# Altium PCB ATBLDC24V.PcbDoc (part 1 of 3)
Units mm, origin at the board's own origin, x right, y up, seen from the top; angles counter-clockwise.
Board outline 135 x 125 mm, 4 copper layers (Top Layer, GND, PWR/Signal, Bottom Layer), stack 1.716 mm thick; 340 components, 168 nets, 921 pads, 872 vias.
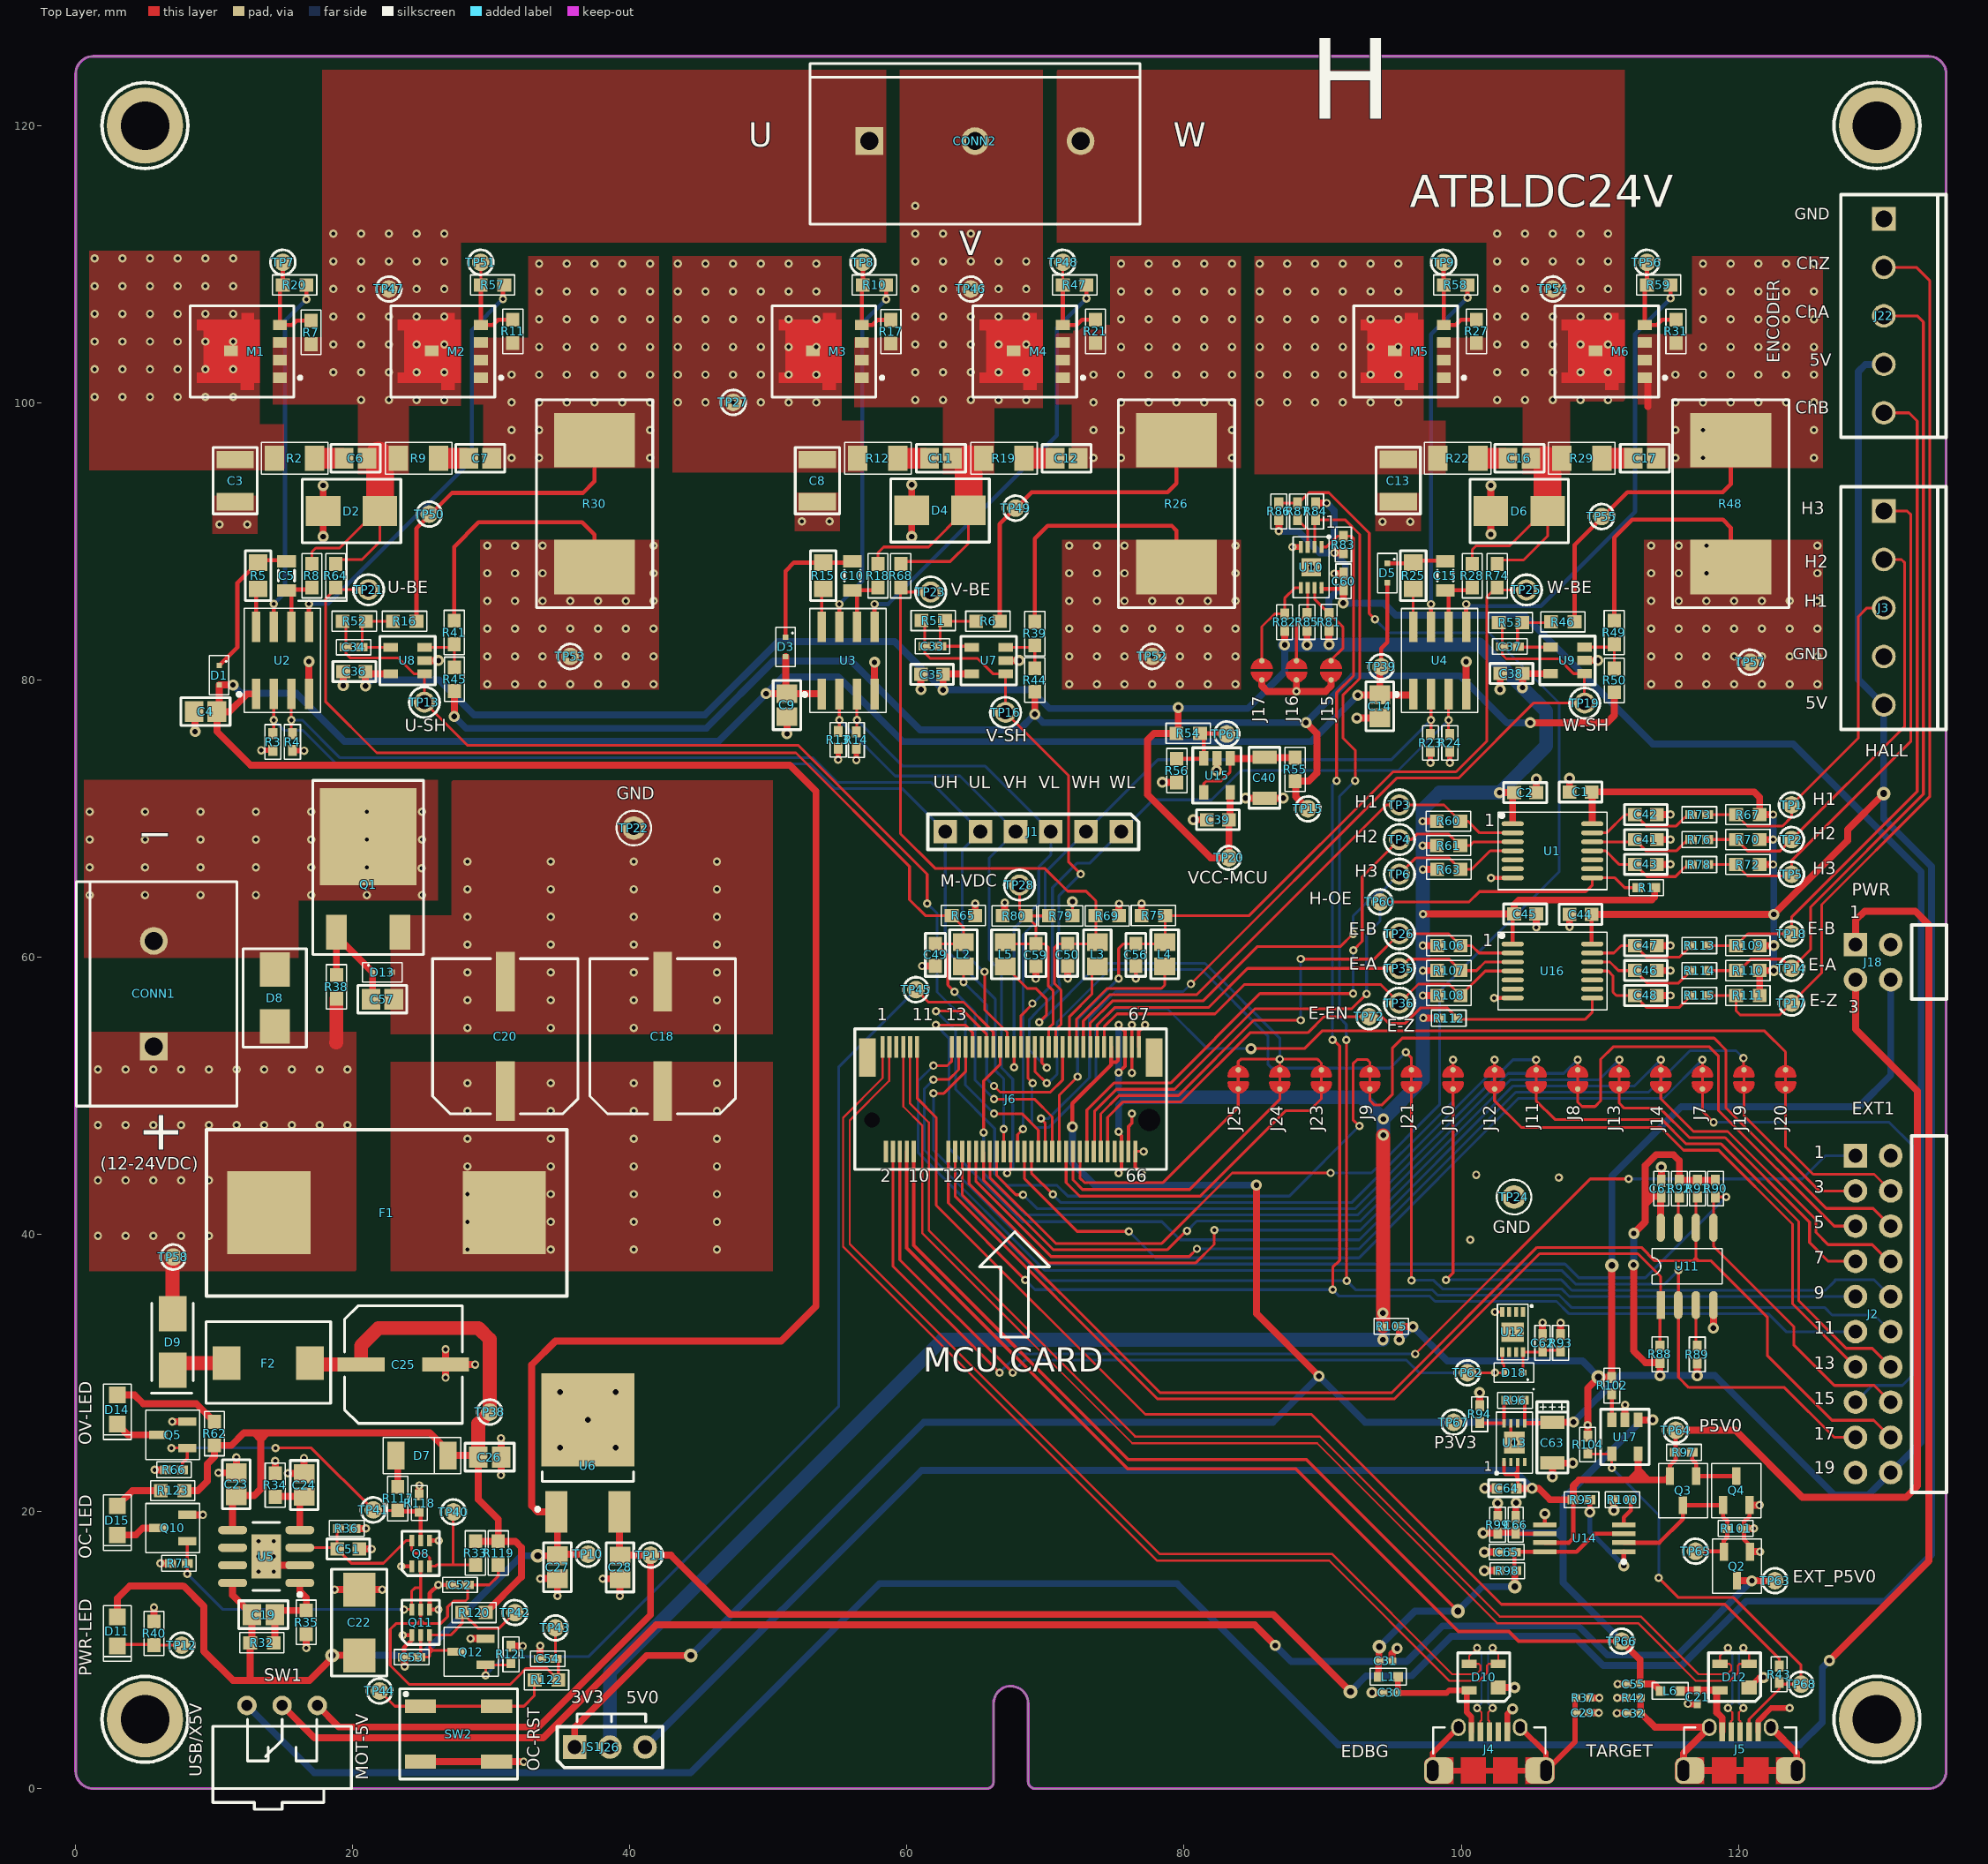
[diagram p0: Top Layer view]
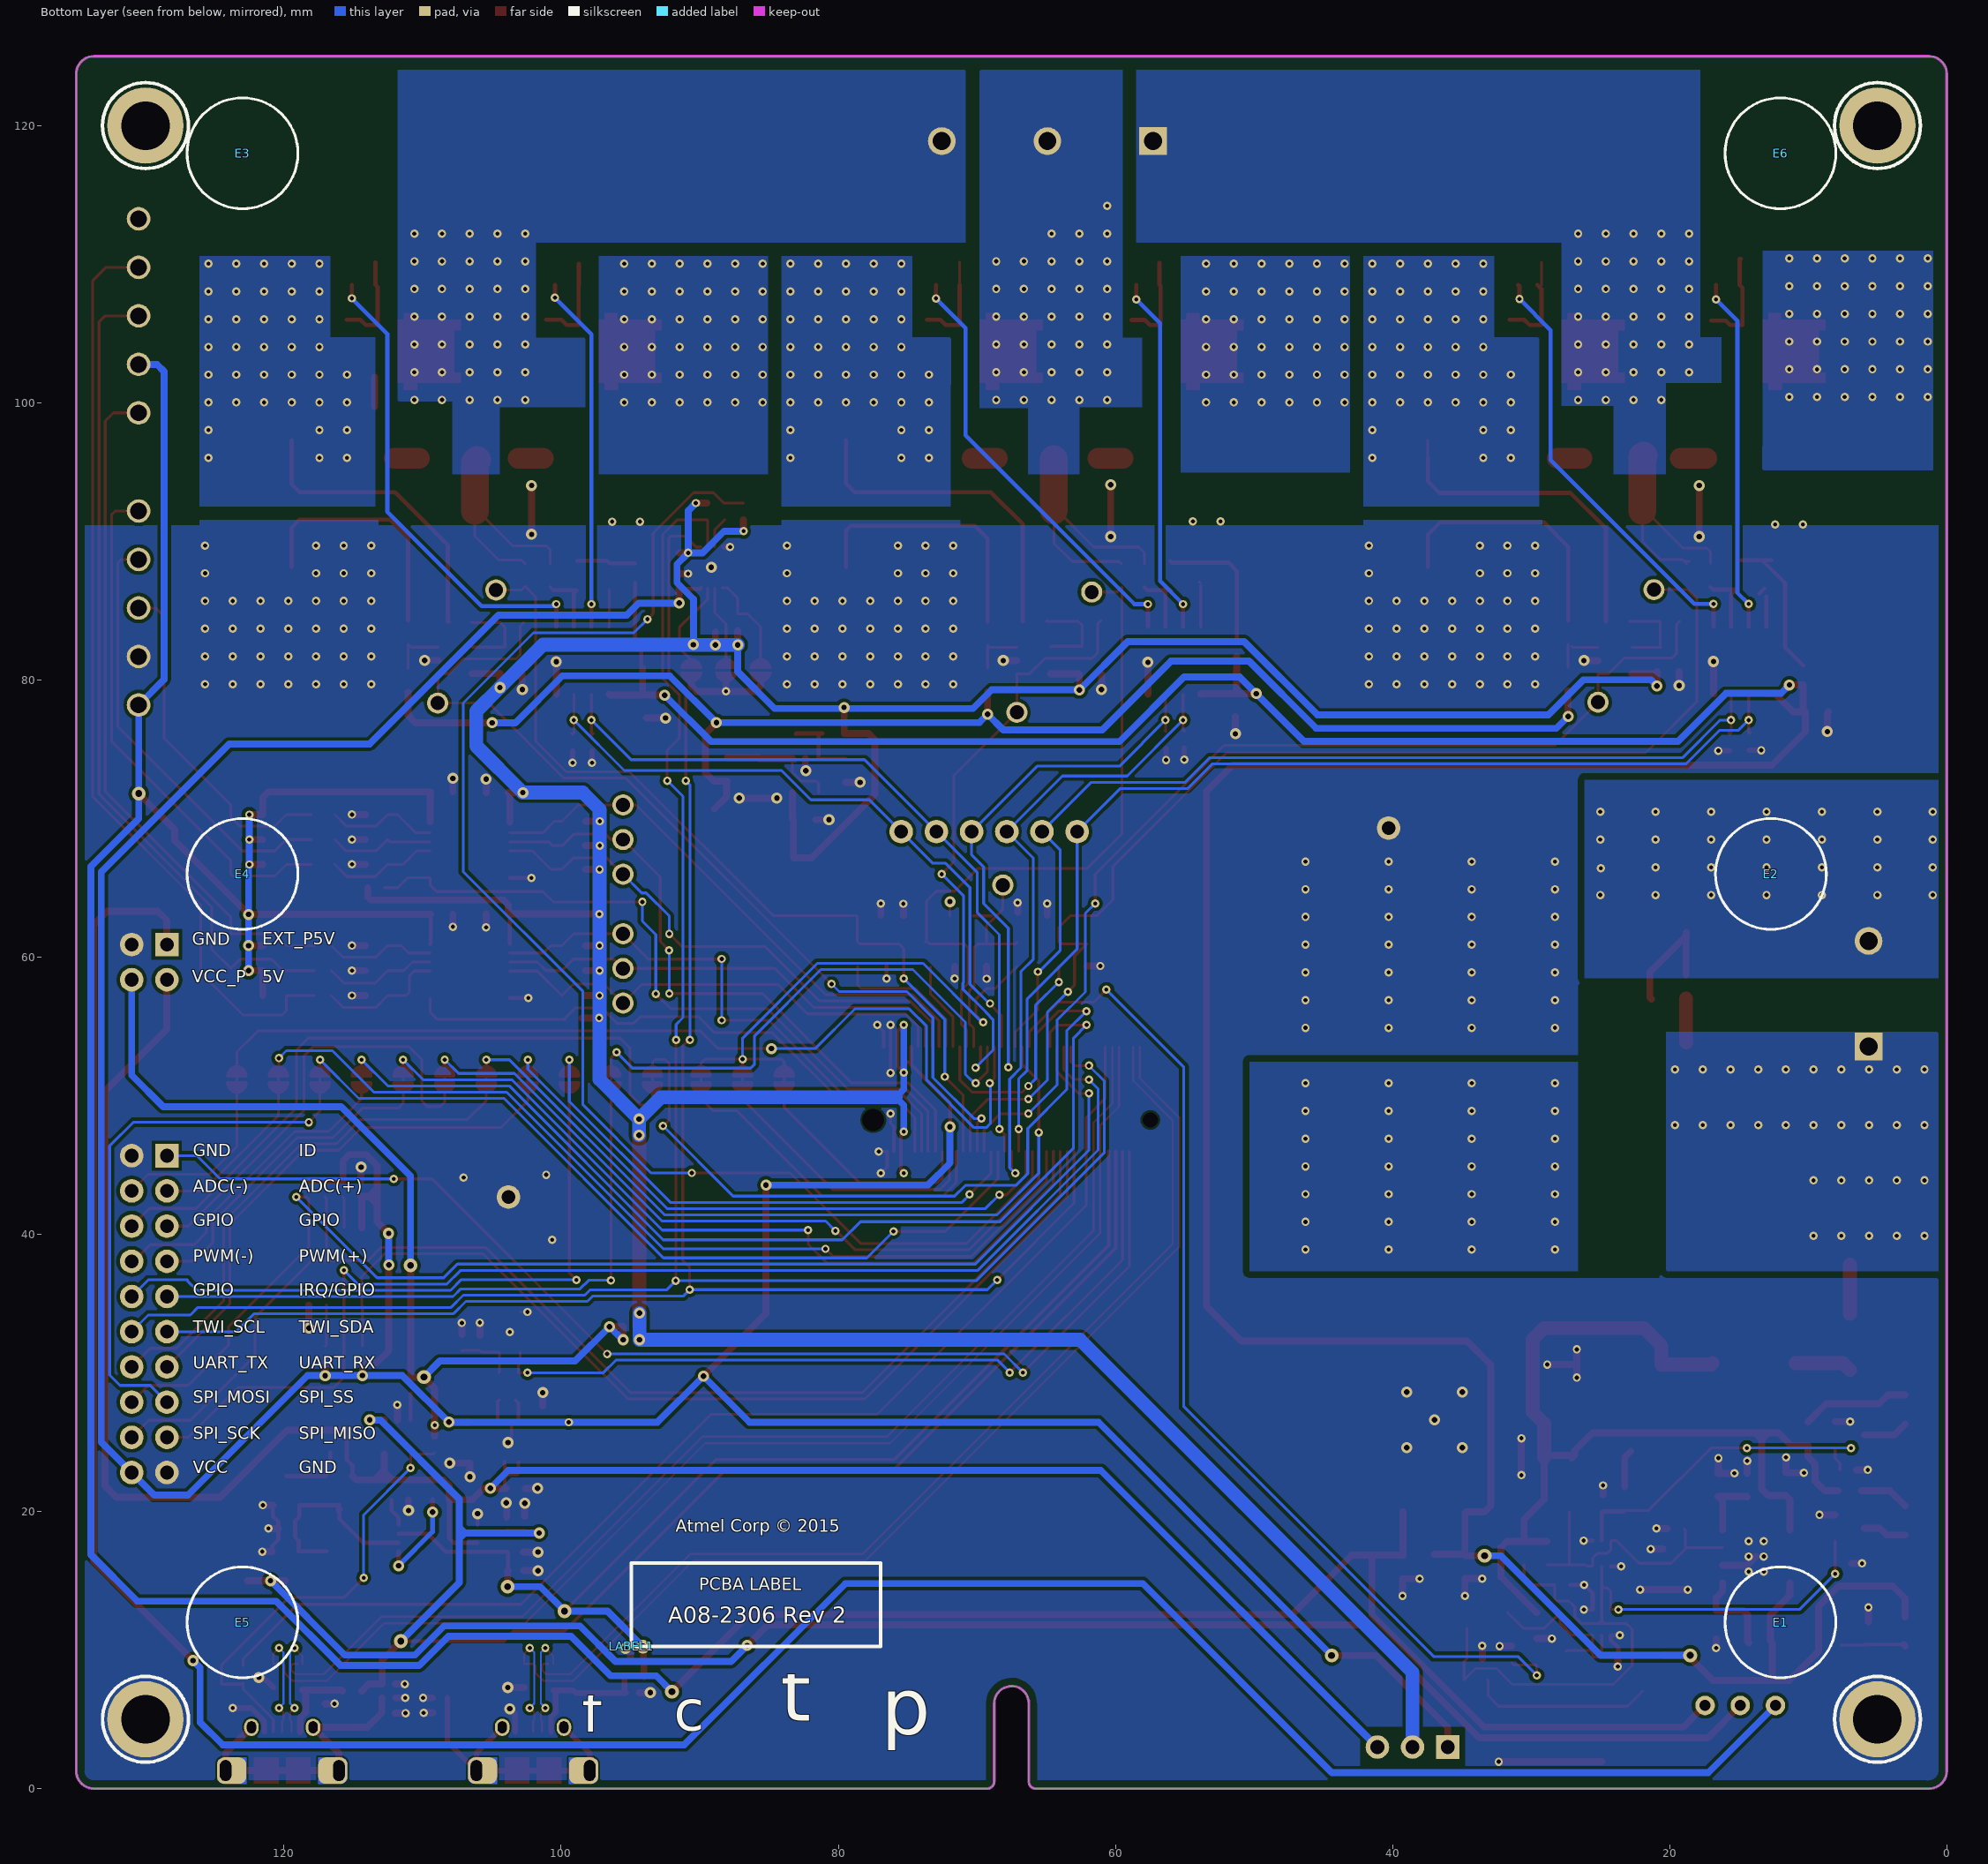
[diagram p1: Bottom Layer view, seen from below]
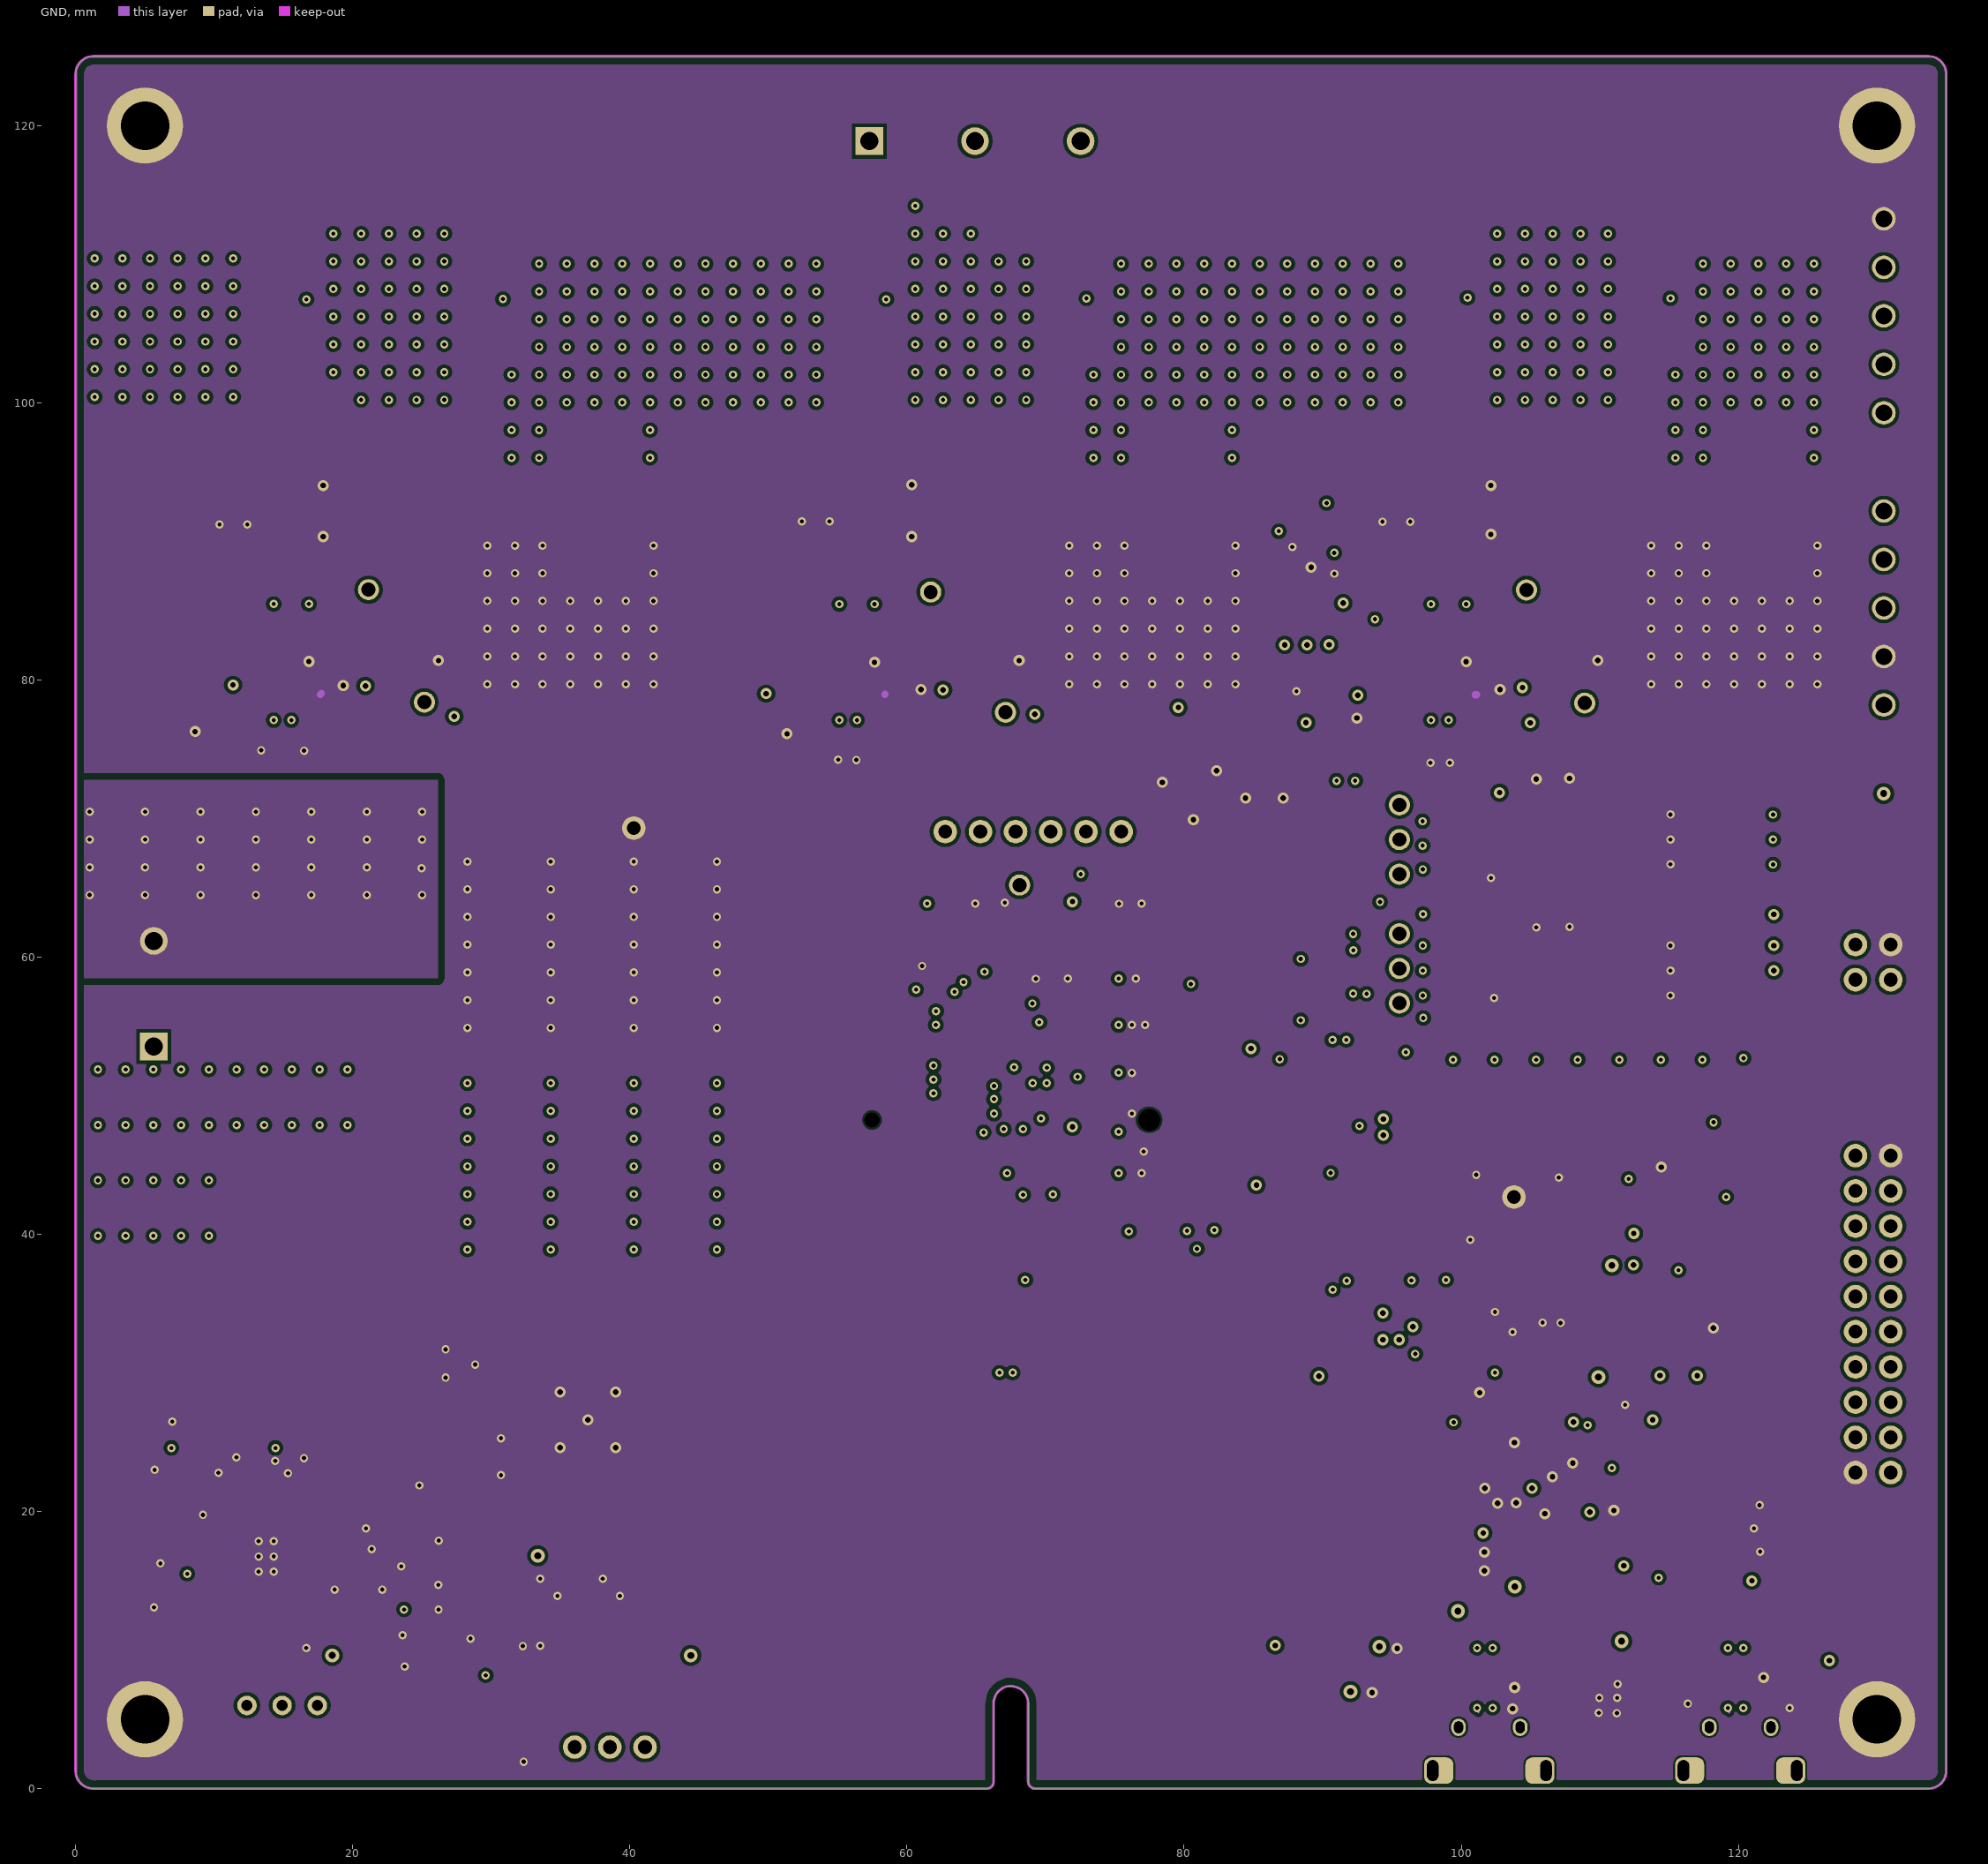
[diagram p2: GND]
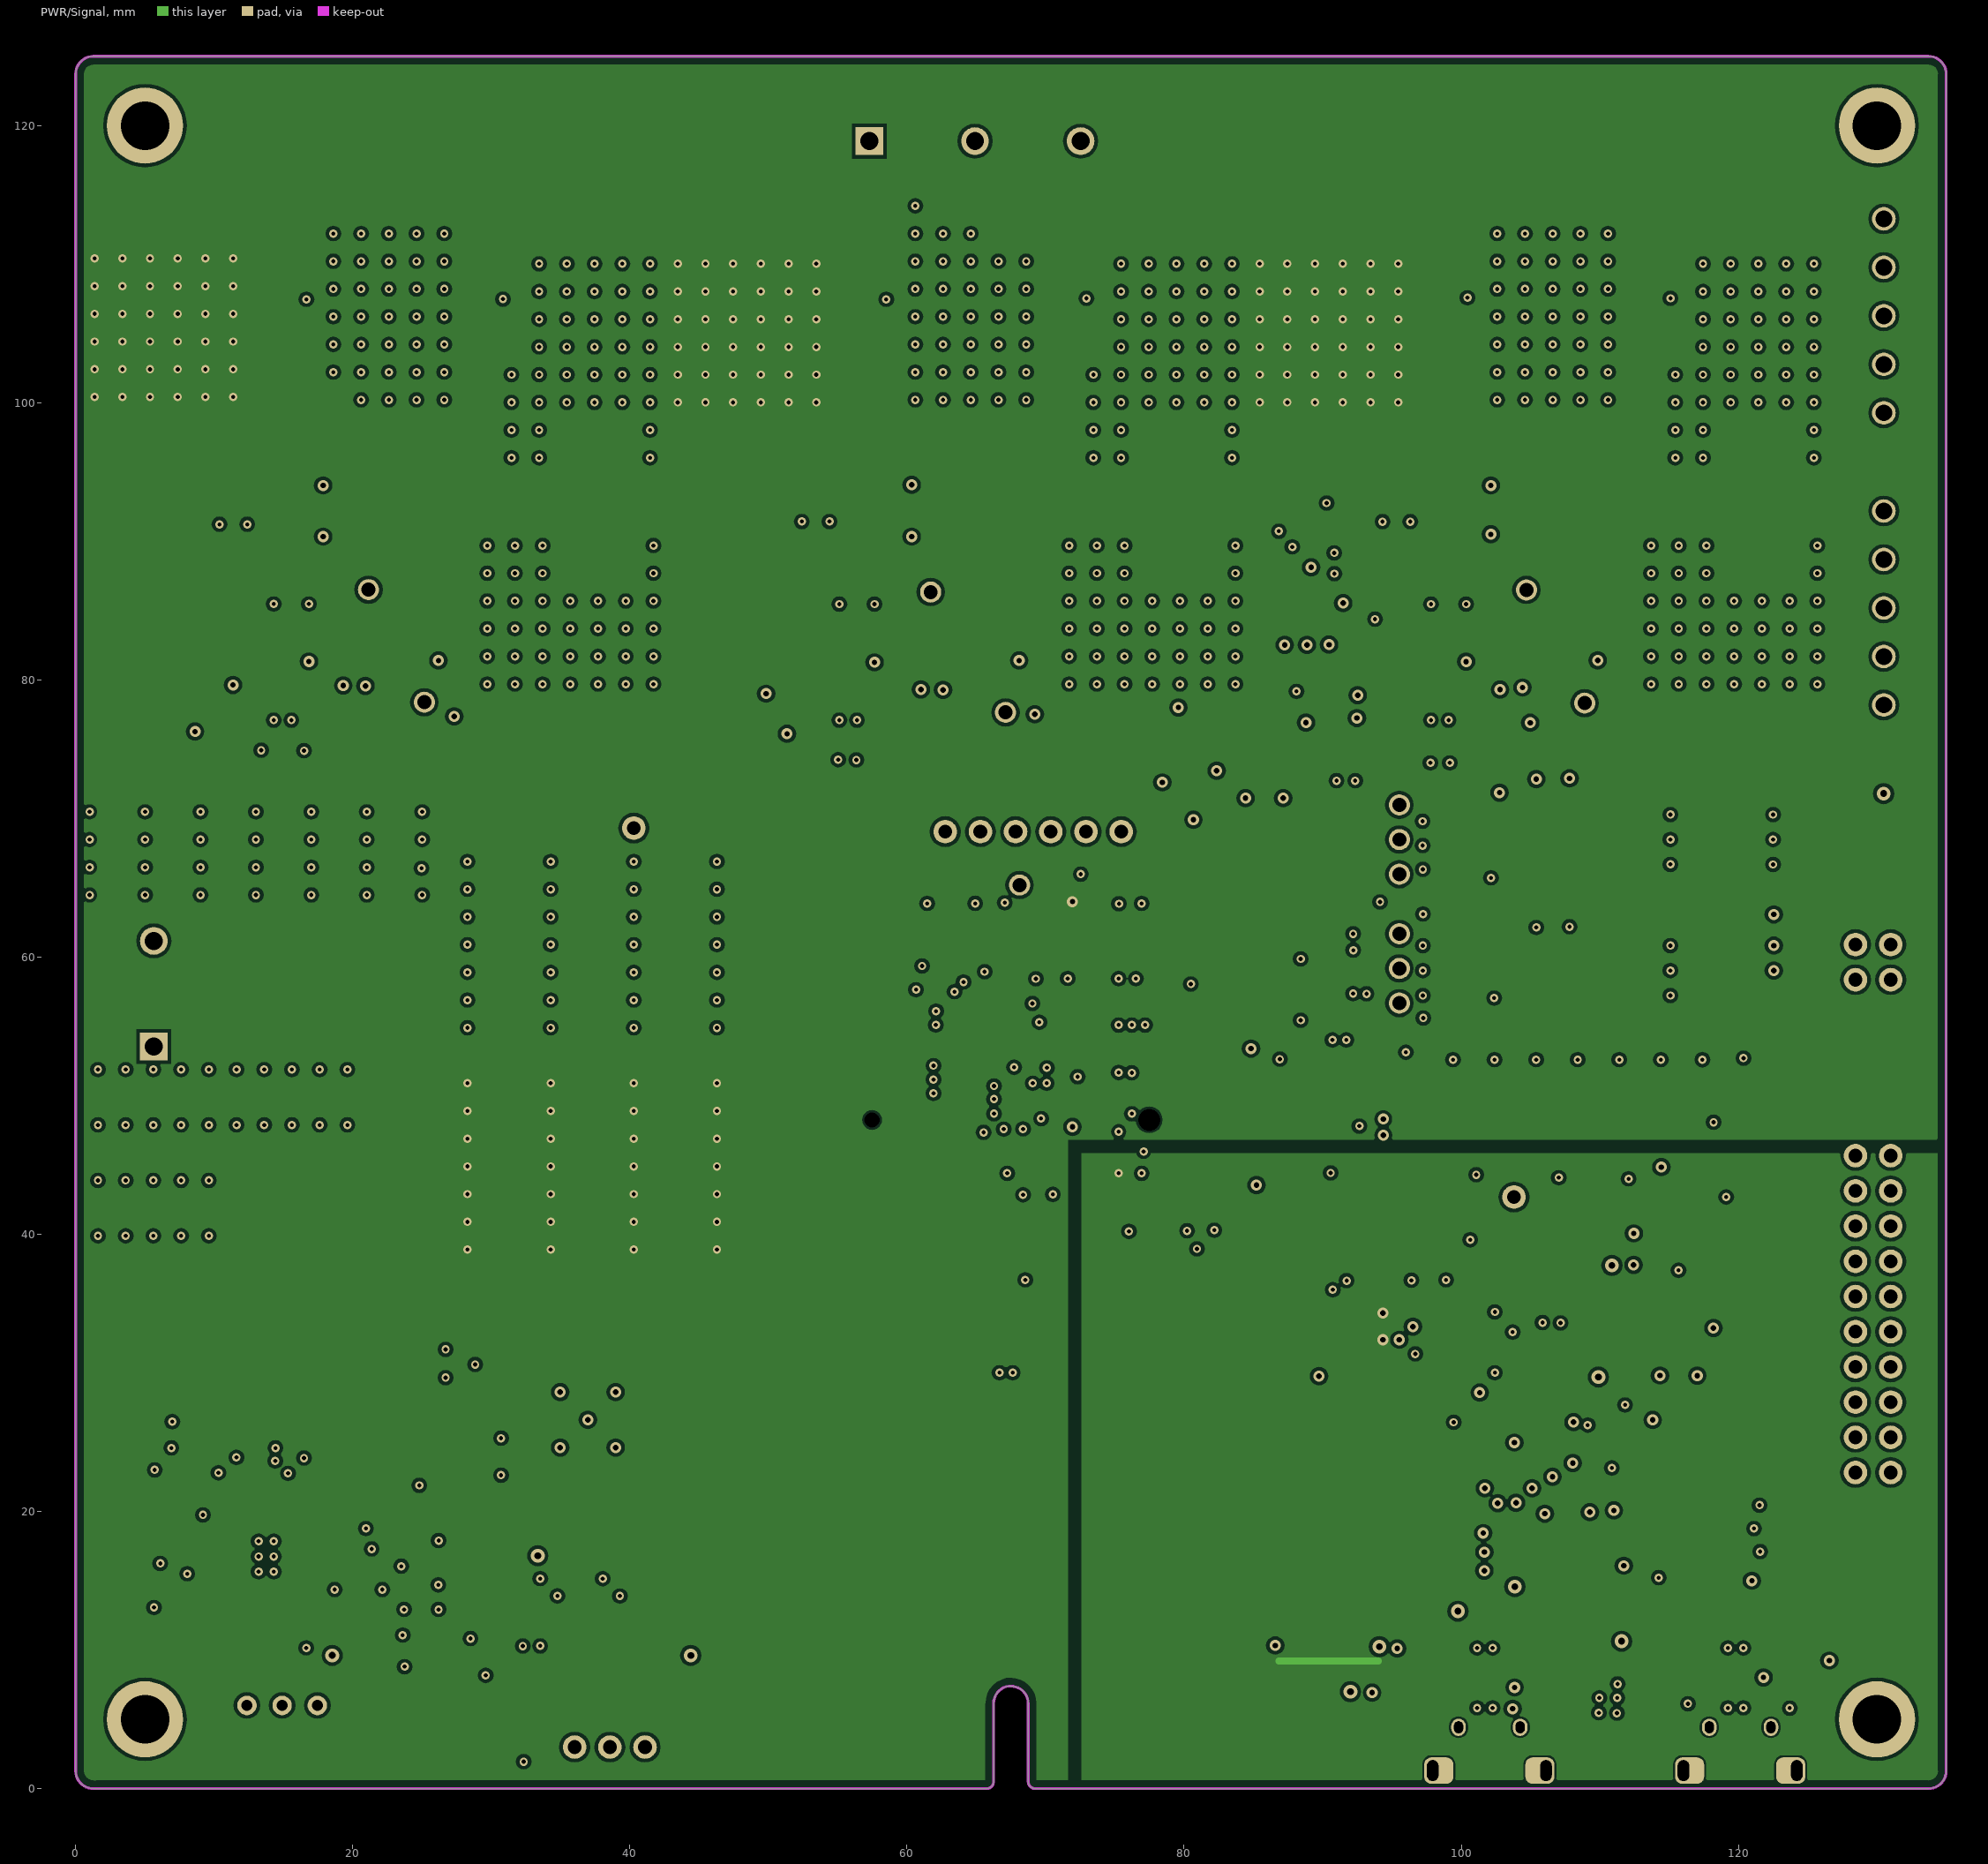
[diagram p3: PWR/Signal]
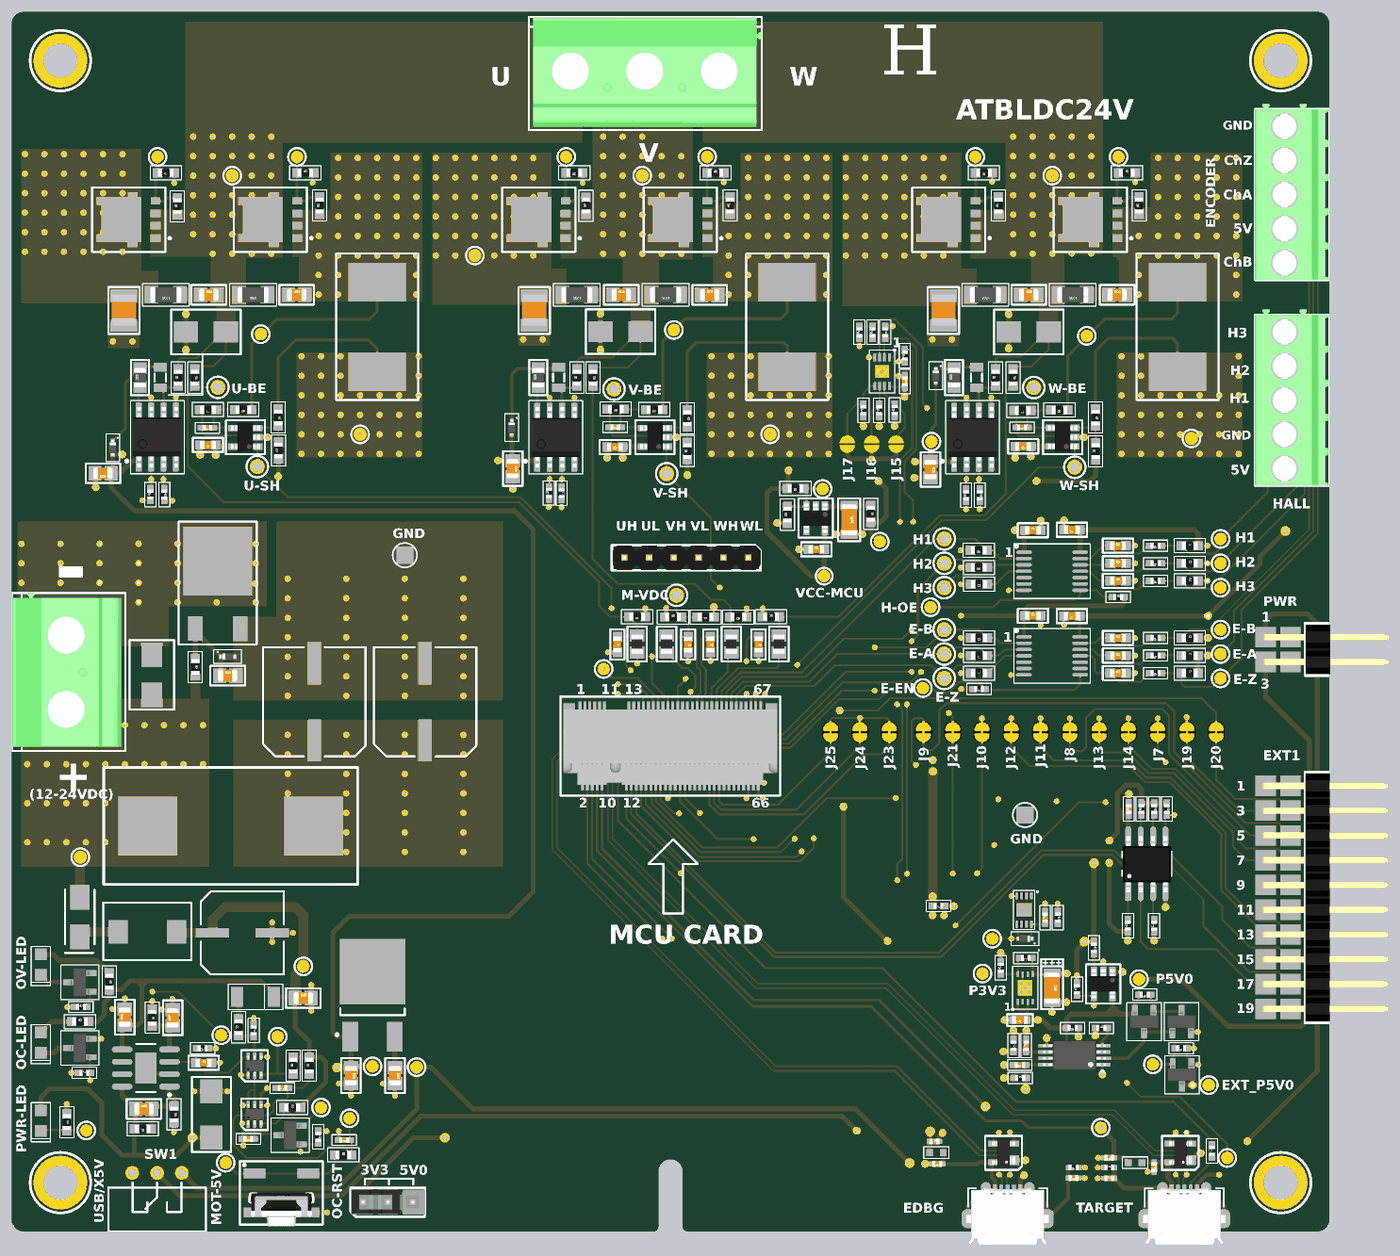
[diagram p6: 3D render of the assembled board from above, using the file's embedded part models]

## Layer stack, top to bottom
Top Solder: solder mask 0.0102, Solder Resist, Dk 3.5
Top Layer: signal copper 0.07
Dielectric1: prepreg 0.118, FR-4, Dk 4.2
GND: signal copper 0.07
Dielectric2: core 1.2, Dk 4.2
PWR/Signal: signal copper 0.07
Dielectric3: prepreg 0.118, Dk 4.2
Bottom Layer: signal copper 0.07
Bottom Solder: solder mask 0.0102, Solder Resist, Dk 3.5

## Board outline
1.27,0 65.75,0 ccw(c65.75,0.5) 66.25,0.5 66.25,6.15 cw(c67.5,6.15) 67.5,7.4 67.5,7.39 cw(c67.5,6.14) 68.75,6.14 68.75,0.5 ccw(c69.25,0.5) 69.25,0 133.73,0 ccw(c133.73,1.27) 135,1.27 135,123.73 ccw(c133.73,123.73) 133.73,125 1.27,125 ccw(c1.27,123.73) 0,123.73 0,1.27 ccw(c1.27,1.27)

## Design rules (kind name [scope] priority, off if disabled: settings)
AssemblyTestPointUsage "Schematic Assembly Testpoint Usage_3" [InNet('EDBG_USB_HS_N')] p1: valid=1
AssemblyTestPointUsage "Schematic Assembly Testpoint Usage_2" [InNet('EDBG_USB_HS_P')] p2: valid=1
AssemblyTestPointUsage "Schematic Assembly Testpoint Usage_1" [InNet('TARGET_USB_HS_N')] p3: valid=1
AssemblyTestPointUsage "Schematic Assembly Testpoint Usage" [InNet('TARGET_USB_HS_P')] p4: valid=1
AssemblyTestPointUsage [All] p5 off:
AssemblyTestpoint [(IsPad And (OnTopLayer Or OnBottomLayer))] p1: testpointundercomponent=TRUE minsize=1.016 maxsize=2.54 preferedsize=1.27 minholesize=0 maxholesize=0 preferedholesize=0 testpointgrid=0.025 usegrid=FALSE gridtolerance=0 allowsidetop=TRUE
Clearance Clearance_24V [InPolygon vs InPolygon] p1: gap=0.5
Clearance Clearance_1 [(OnLayer('Keep-Out Layer'))] p2: gap=0.5
Clearance Clearance_Socket [All vs (HasFootprint('AP8-00916') or HasFootprint('AP6-00186') or hasfootprint('AP1-00001')or hasfootprint('AP4-00001')or hasfootprint('AP8-00852')OR HASFOOTPRINT('AP6-00409') )] p3: gap=0.15
Clearance [All] p4: gap=0.25
DiffPairsRouting [All] p1: maxlimit=0.33 minlimit=0.33 mostfreqgap=0.33 toplayer_minwidth=0.381 toplayer_maxwidth=0.381 toplayer_prefwidth=0.381 midlayer1_minwidth=0.381 midlayer1_maxwidth=0.381 midlayer1_prefwidth=0.381 midlayer2_minwidth=0.381 midlayer2_maxwidth=0.381 midlayer2_prefwidth=0.381 bottomlayer_minwidth=0.381 bottomlayer_maxwidth=0.381 bottomlayer_prefwidth=0.381 maxuncoupledlength=12.7
FabricationTestPointUsage [All] p1 off: valid=0 allowmultiple=FALSE
FabricationTestpoint [All] p1 off: side=3 testpointundercomponent=TRUE minsize=1.016 maxsize=2.54 preferedsize=1.524 minholesize=0 maxholesize=1.016 preferedholesize=0.813 testpointgrid=0.025 allowsidetop=TRUE allowsidebottom=TRUE usegrid=TRUE gridtolerance=0
HoleSize [All] p1: absolutevalues=TRUE maxlimit=4 minlimit=0.025 maxpercent=80.000 minpercent=20.000
MinimumSolderMaskSliver [All] p1: minsoldermaskwidth=0.1
PlaneClearance [All] p1: clearance=0.4
PlaneConnect [All] p1: planeconnectstyle=Direct reliefexpansion=0.508 reliefentries=4 reliefconductorwidth=0.254 reliefairgap=0.254
PolygonConnect PolygonConnect_1 [(HasFootprint('AP2-00004')OR HasFootprint('AP4-00106')OR HasFootprint('AP8-00249') OR HasFootprint('AP5-00048') or IsVia )] p1: connectstyle=Direct reliefconductorwidth=0.254 reliefentries=4 polygonreliefangle="90 Angle" airgapwidth=0.254
PolygonConnect [All] p2: connectstyle=Direct reliefconductorwidth=0.254 reliefentries=4 polygonreliefangle="90 Angle" airgapwidth=0.254
RoutingVias [All] p1: holewidth=0.2 width=0.4 viastyle="Through Hole" minholewidth=0.2 minwidth=0.4 maxholewidth=0.4 maxwidth=0.8
SilkToSilkClearance [All] p1: silktosilkclearance=0.1
SilkToSolderMaskClearance SilkscreenOverComponentPads [IsPad] p1: minsilkscreentomaskgap=0.091 clearancetoexposedcopper=TRUE
SolderMaskExpansion SolderMaskExpansion_Tenting [IsVia AND NOT (IsFabTestpoint OR IsAssyTestpoint)] p1: expansion=-2
SolderMaskExpansion [All] p2: expansion=0.025
Width [All] p1: maxlimit=3 minlimit=0.15 preferedwidth=0.2 minimp=50.000000 maximp=50.000000 favimp=50.000000
19 further rules are at their usual default settings.

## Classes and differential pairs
component class Connector: C21 C29 C30 C31 C32 C55 CONN1 CONN2 D10 D12 J1 J2 J4 J5 L1 L6 R37 R42 R43
component class HALL_ENCODER: C1 C2 C41 C42 C43 C44 C45 C46 C47 C48 J3 J22 R1 R60 R61 R63 R67 R70 R72 R73 R76 R78 R106 R107 R108 R109 R110 R111 R112 R113 R114 R115 TP1 TP2 TP3 TP4 TP5 TP6 TP14 TP17 TP18 TP26 TP35 TP36 TP60 TP72 U1 U16
component class Driver: C3 C4 C5 C6 C7 C8 C9 C10 C11 C12 C13 C14 C15 C16 C17 C33 C34 C35 C36 C37 C38 D1 D2 D3 D4 D5 D6 M1 M2 M3 M4 M5 M6 R2 R3 R4 R5 R6 R7 R8 R9 R10 R11 R12 R13 R14 R15 R16 R17 R18 R19 R20 R21 R22 R23 R24 R25 R26 R27 R28 R29 R30 R31 R39 R41 R44 R45 R46 R47 R48 R49 R50 R51 R52 R53 R57 R58 R59 TP7 TP8 TP9 TP13 TP16 TP19 TP46 TP47 TP48 TP49 TP50 TP51 TP52 TP53 TP54 TP55 TP56 TP57 U2 U3 U4 U7 U8 U9
component class MCU: J6 J7 J8 J9 J10 J11 J12 J13 J14 J19 J20 J21 J23 J24 J25 TP308
component class ATBLDC24V_TopLevel: E1 E2 E3 E4 E5 E6 LABEL1
component class PS: C18 C19 C20 C22 C23 C24 C25 C26 C27 C28 C51 C52 C53 C54 C57 D7 D8 D9 D11 D13 D14 D15 F1 F2 Q1 Q5 Q8 Q10 Q11 Q12 R32 R33 R34 R35 R36 R38 R40 R62 R66 R71 R117 R118 R119 R120 R121 R122 R123 SW1 SW2 TP10 TP11 TP12 TP22 TP24 TP38 TP39 TP40 TP41 TP42 TP43 TP44 TP45 TP58 U5 U6
component class sensor: C39 C40 C49 C50 C56 C59 L2 L3 L4 L5 R54 R55 R56 R64 R65 R68 R69 R74 R75 R79 R80 TP15 TP21 TP23 TP25 TP27 TP28 TP61 U15
component class Temerature_Sensor: C60 C61 C62 D18 J15 J16 J17 R81 R82 R83 R84 R85 R86 R87 R88 R89 R90 R91 R92 R93 TP62 U10 U11 U12
component class Triple_Input_Power_Supply: C63 C64 C65 C66 J18 J26 JS1 Q2 Q3 Q4 R94 R95 R96 R97 R98 R99 R100 R101 R102 R104 R105 TP20 TP63 TP64 TP65 TP66 TP67 TP68 U13 U14 U17
differential pair EDBG_USB_HS: +EDBG_USB_HS_P -EDBG_USB_HS_N
differential pair TARGET_USB_HS: +TARGET_USB_HS_P -TARGET_USB_HS_N

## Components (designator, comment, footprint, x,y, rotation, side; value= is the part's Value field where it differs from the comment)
C1 "CAP-NONPOL" AP1-00002 108.616,71.918 r180 top
C2 "CAP-NONPOL" AP1-00002 104.616,71.868 r0 top
C3 "Two similar MPNs from TDK, new and old part number." AP1-00015 11.51,94.385 r270 top
C4 "CAP-NONPOL" AP1-00003 9.367,77.709 r180 top
C5 "CAP-NONPOL" AP1-00069 15.216,87.518 r270 top
C6 "CAP-NONPOL" AP1-00003 20.2,96 r0 top
C7 "CAP-NONPOL" AP1-00003 29.2,96 r0 top
C8 "Two similar MPNs from TDK, new and old part number." AP1-00015 53.536,94.385 r270 top
C9 "CAP-NONPOL" AP1-00003 51.338,78.183 r270 top
C10 "CAP-NONPOL" AP1-00069 56.05,87.518 r270 top
C11 "CAP-NONPOL" AP1-00003 62.45,96 r0 top
C12 "CAP-NONPOL" AP1-00003 71.514,95.985 r0 top
C13 "Two similar MPNs from TDK, new and old part number." AP1-00015 95.453,94.386 r270 top
C14 "CAP-NONPOL" AP1-00003 94.127,78.1 r270 top
C15 "CAP-NONPOL" AP1-00069 98.844,87.518 r270 top
C16 "CAP-NONPOL" AP1-00003 104.2,96 r0 top
C17 "CAP-NONPOL" AP1-00003 113.25,96 r0 top
C18 "CAP-POL" AP1-00025 42.357,54.288 r90 top
C19 "CAP-NONPOL" AP1-00003 13.55,12.55 r0 top
C20 "CAP-POL" AP1-00025 31.007,54.288 r90 top
C21 "1 nF C0G" AP1-00053 117.039,6.597 r270 top
C22 "CAP-POL" AP1-00013 20.47,11.985 r90 top
C23 "CAP-NONPOL" AP1-00003 11.595,21.962 r90 top
C24 "CAP-NONPOL" AP1-00003 16.5,21.9 r90 top
C25 "47uF/63V" AP1-00012 23.65,30.6 r0 top
C26 "CAP-NONPOL" AP1-00003 29.877,23.918 r0 top
C27 "CAP-NONPOL" AP1-00003 34.767,15.976 r270 top
C28 "CAP-NONPOL" AP1-00003 39.278,15.97 r270 top
C29 "CAP-NONPOL" AP1-00053 108.774,5.473 r180 top
C30 "1 nF C0G" AP1-00053 94.832,6.923 r180 top
C31 "1 nF C0G" AP1-00053 94.532,9.223 r0 top
C32 "CAP-NONPOL" AP1-00053 112.439,5.447 r0 top
C33 "CAP-NONPOL" AP1-00001 61.835,82.431 r180 top
C34 "CAP-NONPOL" AP1-00001 20.06,82.358 r180 top
C35 "CAP-NONPOL" AP1-00002 61.8,80.4 r180 top
C36 "CAP-NONPOL" AP1-00002 20.11,80.608 r180 top
C37 "CAP-NONPOL" AP1-00001 103.511,82.409 r180 top
C38 "CAP-NONPOL" AP1-00002 103.621,80.466 r180 top
C39 "CAP-NONPOL" AP1-00002 82.435,69.912 r0 top
C40 "CAP-NONPOL" AP1-00026 85.798,72.942 r270 top
C41 "MPN back-ported from Escatec 29-09-2009" AP1-00002 113.331,68.484 r0 top
C42 "MPN back-ported from Escatec 29-09-2009" AP1-00002 113.331,70.284 r0 top
C43 "MPN back-ported from Escatec 29-09-2009" AP1-00002 113.33,66.691 r0 top
C44 "CAP-NONPOL" AP1-00002 108.616,63.081 r180 top
C45 "CAP-NONPOL" AP1-00002 104.616,63.108 r0 top
C46 "MPN back-ported from Escatec 29-09-2009" AP1-00002 113.33,59.028 r0 top
C47 "MPN back-ported from Escatec 29-09-2009" AP1-00002 113.33,60.828 r0 top
C48 "MPN back-ported from Escatec 29-09-2009" AP1-00002 113.33,57.228 r0 top
C49 "MPN back-ported from Escatec 29-09-2009" AP1-00002 62.056,60.16 r270 top
C50 "MPN back-ported from Escatec 29-09-2009" AP1-00002 71.586,60.16 r270 top
C51 "CAP-NONPOL" AP1-00002 19.671,17.289 r0 top
C52 "CAP-NONPOL" AP1-00001 27.74,14.7 r180 top
C53 "CAP-NONPOL" AP1-00001 24.248,9.486 r180 top
C54 "CAP-NONPOL" AP1-00001 34.073,9.367 r180 top
C55 "1 nF C0G" AP1-00053 112.439,7.547 r180 top
C56 "MPN back-ported from Escatec 29-09-2009" AP1-00002 76.514,60.16 r270 top
C57 "CAP-NONPOL" AP1-00003 22.132,56.966 r0 top
C59 "MPN back-ported from Escatec 29-09-2009" AP1-00002 69.3,60.15 r270 top
C60 "100n" AP1-00001 91.507,87.116 r270 top
C61 "100n" AP1-00001 114.445,43.29 r90 top
C62 "Recommended by Escatec. No datasheet available yet." AP1-00001 105.867,32.164 r90 top
C63 "CAP-POL" AP1-00036 106.584,24.967 r270 top
C64 "CAP-NONPOL" AP1-00039 103.284,21.667 r180 top
C65 "CAP-NONPOL" AP1-00001 103.284,17.067 r180 top
C66 "CAP-NONPOL" AP1-00001 103.934,19.042 r90 top
CONN1 "Screw Terminal Block 2-way" AP8-00979 5.639,53.547 r90 top
CONN2 "Farnell no.: 2008004" AP8-00980 57.288,118.881 r0 top
D1 "Farnell# 1615809" AP4-00036 10.357,80.338 r270 top
D2 "TransGuard" AP4-00002 19.907,92.188 r180 top
D3 "Farnell# 1615809" AP4-00036 51.238,82.383 r270 top
D4 "TransGuard" AP4-00002 62.385,92.231 r180 top
D5 "Farnell# 1615809" AP4-00036 94.671,87.709 r270 top
D6 "TransGuard" AP4-00002 104.187,92.188 r180 top
D7 "ZENER_SMD_12" AP4-00142 24.99,24.037 r180 top
D8 "TransGuard" AP4-00002 14.37,57.05 r90 top
D9 "SCHOTTKY_SMD_12" AP4-00038 6.992,32.228 r90 top
D10 "PRTR5V0U2X" AP4-00001 102.675,7.298 r180 top
D11 "LED_12" AP4-00013 3,11.35 r90 top
D12 "PRTR5V0U2X" AP4-00001 120.775,7.297 r180 top
D13 "ZENER_SMD_12" AP4-00036 22.132,58.91 r0 top
D14 "LED_12" AP4-00013 3,27.35 r90 top
D15 "LED_12" AP4-00013 3,19.35 r90 top
D18 "Farnell# 1615809" AP4-00036 103.799,30.01 r180 top
E1 "" AP8-00192 12,12 r180 bottom
E2 "" AP8-00192 12.689,66 r180 bottom
E3 "" AP8-00192 123,118 r180 bottom
E4 "" AP8-00192 123,66 r180 bottom
E5 "RUBBER FEET" AP8-00192 123,12 r180 bottom
E6 "RUBBER FEET" AP8-00192 12,118 r180 bottom
F1 "FUSE" AP8-00249 22.44,41.55 r0 top
F2 "Farnell# 117-5872" AP2-00018 13.9,30.7 r180 top
J1 "HEADER 1x6" AP8-00177 69.107,69.05 r180 top
J2 "HEADER 2x10" AP8-00622 129.73,34.239 r270 top locked
J3 "HEADER 1x5" AP8-00935 130.5,92.19 r270 top
J4 "2,000 pieces per reel" AP8-00852 102.03,1.3 r0 top
J5 "2,000 pieces per reel" AP8-00852 120.13,1.3 r0 top
J6 "HEADER_67" AP8-00916 67.48,49.75 r0 top
J7 "PCB trace only" AP9-00035 117.407,51.173 r90 top net-tie
J8 "PCB trace only" AP9-00035 108.407,51.173 r90 top net-tie
J9 "PCB trace only" AP9-00035 93.407,51.173 r90 top net-tie
J10 "PCB trace only" AP9-00035 99.407,51.173 r90 top net-tie
J11 "PCB trace only" AP9-00035 105.407,51.173 r90 top net-tie
J12 "PCB trace only" AP9-00035 102.407,51.173 r90 top net-tie
J13 "PCB trace only" AP9-00035 111.407,51.173 r90 top net-tie
J14 "PCB trace only" AP9-00035 114.407,51.173 r90 top net-tie
J15 "Open Link" AP9-00078 90.608,80.692 r90 top net-tie
J16 "Open Link" AP9-00078 88.108,80.692 r90 top net-tie
J17 "Open Link" AP9-00078 85.608,80.692 r90 top net-tie
J18 "HEADER 2x2" AP8-00628 129.73,59.639 r270 top locked
J19 "PCB trace only" AP9-00035 120.407,51.173 r90 top net-tie
J20 "PCB trace only" AP9-00035 123.407,51.173 r90 top net-tie
J21 "PCB trace only" AP9-00035 96.407,51.173 r90 top net-tie
J22 "HEADER 1x5" AP8-00935 130.5,113.27 r270 top
J23 "PCB trace only" AP9-00035 89.907,51.172 r270 top net-tie
J24 "PCB trace only" AP9-00035 86.907,51.172 r270 top net-tie
J25 "PCB trace only" AP9-00035 83.907,51.172 r270 top net-tie
J26 "Same as A08-1614 but with 1mm hole for optimal reflow soldering (no misalignment of the component)" AP8-00745 38.55,2.997 r0 top
JS1 "To be used by request from ESCATEC" AP8-00525 37.3,3 r180 top
L1 "BLM18PG471SN1" AP3-00005 94.732,8.073 r180 top
L2 "INDUCTOR" AP3-00002 63.779,60.8 r270 top
L3 "INDUCTOR" AP3-00002 73.433,60.8 r270 top
L4 "INDUCTOR" AP3-00002 78.3,60.8 r270 top
L5 "INDUCTOR" AP3-00002 66.8,60.8 r270 top
L6 "BLM18PG471SN1" AP3-00005 115.089,7.047 r180 top
LABEL1 "PCBA_LABEL" AP8-00317 94.933,10.269 r180 bottom
M1 "NTMFS5C646NL" AP5-00048 14.75,103.7 r90 top
M2 "NTMFS5C646NL" AP5-00048 29.25,103.7 r90 top
M3 "NTMFS5C646NL" AP5-00048 56.75,103.7 r90 top
M4 "NTMFS5C646NL" AP5-00048 71.25,103.7 r90 top
M5 "NTMFS5C646NL" AP5-00048 98.75,103.7 r90 top
M6 "NTMFS5C646NL" AP5-00048 113.25,103.7 r90 top
Q1 "MOSFET_N_DPAK" AP5-00005 21.107,68.688 r0 top
Q2 "MOSFET_P_GSD" AP5-00002 119.9,16.05 r270 top
Q3 "MOSFET_P_GSD" AP5-00002 116.012,21.499 r270 top
Q4 "MOSFET_N_GSD" AP5-00002 119.85,21.5 r90 top
Q5 "MOSFET_N_GSD" AP5-00002 7,25.529 r180 top
Q8 "Same as 2N7002 but with two MOSFETs in one package" AP5-00001 24.9,16.971 r90 top
Q10 "MOSFET_N_GSD" AP5-00002 7,18.8 r180 top
Q11 "Same as 2N7002 but with two MOSFETs in one package" AP5-00001 24.9,12 r90 top
Q12 "NPN BEC" AP5-00002 28.541,9.875 r180 top
R1 "R2" AP2-00000 113.361,65.014 r0 top
R2 "R2" AP2-00003 15.8,96 r180 top
R3 "R2" AP2-00000 14.226,75.525 r90 top
R4 "R2" AP2-00000 15.646,75.525 r270 top
R5 "R2" AP2-00002 13.165,87.518 r90 top
R6 "Farnell no.: 1717570" AP2-00001 65.84,84.233 r180 top
R7 "R2" AP2-00001 16.985,105.08 r90 top
R8 "R2" AP2-00001 17.049,87.518 r90 top
R9 "R2" AP2-00003 24.75,96 r180 top
R10 "R2" AP2-00001 57.65,108.5 r180 top
R11 "R2" AP2-00001 31.55,105.15 r90 top
R12 "R2" AP2-00003 57.9,96 r180 top
R13 "R2" AP2-00000 55.035,75.681 r90 top
R14 "R2" AP2-00000 56.343,75.663 r270 top
R15 "R2" AP2-00002 53.95,87.518 r90 top
R16 "Farnell no.: 1717570" AP2-00001 23.74,84.233 r180 top
R17 "R2" AP2-00001 58.835,105.13 r90 top
R18 "R2" AP2-00001 57.9,87.518 r90 top
R19 "R2" AP2-00003 67,96 r180 top
R20 "R2" AP2-00001 15.8,108.5 r180 top
R21 "R2" AP2-00001 73.6,105.15 r90 top
R22 "R2" AP2-00003 99.75,96 r180 top
R23 "R2" AP2-00000 97.775,75.456 r90 top
R24 "R2" AP2-00000 99.175,75.456 r270 top
R25 "R2" AP2-00002 96.539,87.518 r90 top
R26 "R2" AP2-00080 79.45,92.722 r90 top
R27 "R2" AP2-00001 101.1,105.15 r90 top
R28 "R2" AP2-00001 100.794,87.518 r90 top
R29 "R2" AP2-00003 108.7,96 r180 top
R30 "R2" AP2-00080 37.45,92.722 r90 top
R31 "R2" AP2-00001 115.5,105.15 r90 top
R32 "R2" AP2-00001 13.436,10.522 r180 top
R33 "R2" AP2-00001 28.85,17 r90 top
R34 "R2" AP2-00001 14.4,21.9 r270 top
R35 "R2" AP2-00001 16.64,12 r270 top
R36 "R2" AP2-00000 19.564,18.768 r180 top
R37 "R2" AP2-00011 108.789,6.547 r180 top
R38 "R2" AP2-00001 18.82,57.856 r270 top
R39 "Farnell no.: 1717570" AP2-00001 69.221,83.342 r270 top
R40 "R2" AP2-00001 5.65,11.2 r270 top
R41 "Farnell no.: 1717570" AP2-00001 27.317,83.423 r270 top
R42 "R2" AP2-00011 112.439,6.547 r0 top
R43 "R2" AP2-00000 122.95,8.25 r90 top
R44 "Farnell no.: 1717597" AP2-00001 69.221,79.992 r90 top
R45 "Farnell no.: 1717597" AP2-00001 27.337,80.048 r90 top
R46 "Farnell no.: 1717570" AP2-00001 107.334,84.19 r180 top
R47 "R2" AP2-00001 72.1,108.5 r0 top
R48 "R2" AP2-00080 119.45,92.722 r90 top
R49 "Farnell no.: 1717570" AP2-00001 111.043,83.419 r270 top
R50 "Farnell no.: 1717597" AP2-00001 111.052,79.967 r90 top
R51 "Farnell no.: 1717597" AP2-00001 61.89,84.283 r180 top
R52 "Farnell no.: 1717597" AP2-00001 20.109,84.233 r180 top
R53 "Farnell no.: 1717597" AP2-00001 103.551,84.141 r180 top
R54 "Farnell no.: 1717597" AP2-00001 80.295,76.147 r180 top
R55 "R2" AP2-00001 88.01,73.545 r270 top
R56 "Farnell no.: 1717597" AP2-00001 79.473,73.459 r90 top
R57 "R2" AP2-00001 30.085,108.5 r0 top
R58 "R2" AP2-00001 99.6,108.5 r180 top
R59 "R2" AP2-00001 114.25,108.5 r0 top
R60 "R2" AP2-00001 99.082,69.806 r180 top
R61 "R2" AP2-00001 99.089,68.048 r180 top
R62 "R2" AP2-00001 10.016,25.614 r270 top
R63 "R2" AP2-00001 99.105,66.329 r180 top
R64 "R2" AP2-00001 18.765,87.518 r270 top
R65 "R2" AP2-00001 64.07,63 r180 top
R66 "R2" AP2-00000 7.1,23 r0 top
R67 "R2" AP2-00001 120.688,70.281 r0 top
R68 "R2" AP2-00001 59.55,87.518 r270 top
R69 "R2" AP2-00001 74.447,62.977 r180 top
R70 "R2" AP2-00001 120.688,68.481 r0 top
R71 "R2" AP2-00000 7.45,16.25 r0 top
R72 "R2" AP2-00001 120.688,66.681 r0 top
R73 "R2" AP2-00000 117.188,70.281 r180 top
R74 "R2" AP2-00001 102.594,87.518 r270 top
R75 "R2" AP2-00001 77.783,63 r0 top
R76 "R2" AP2-00000 117.188,68.481 r180 top
R78 "R2" AP2-00000 117.188,66.681 r180 top
R79 "R2" AP2-00001 71.09,62.977 r180 top
R80 "R2" AP2-00001 67.74,62.977 r0 top
R81 "R2" AP2-00000 90.457,84.191 r90 top
R82 "R2" AP2-00000 87.257,84.166 r90 top
R83 "R2" AP2-00000 91.494,89.768 r90 top
R84 "R2" AP2-00000 89.487,92.162 r270 top
R85 "R2" AP2-00000 88.867,84.172 r90 top
R86 "R2" AP2-00000 86.837,92.162 r90 top
R87 "R2" AP2-00000 88.187,92.162 r90 top
R88 "R2" AP2-00000 114.345,31.34 r90 top
R89 "R2" AP2-00000 117.035,31.33 r90 top
R90 "R2" AP2-00000 118.345,43.29 r270 top
R91 "R2" AP2-00000 117.045,43.29 r270 top
R92 "R2" AP2-00000 115.745,43.29 r90 top
R93 "R2" AP2-00000 107.167,32.164 r270 top
R94 "R2" AP2-00000 101.334,27.017 r90 top
R95 "R2" AP2-00000 108.684,20.842 r180 top
R96 "R2" AP2-00000 103.884,28.017 r180 top
R97 "R2" AP2-00000 116.075,24.267 r180 top
R98 "R2" AP2-00000 103.322,15.726 r0 top
R99 "R2" AP2-00000 102.634,19.042 r270 top
R100 "R2" AP2-00000 111.634,20.842 r0 top
R101 "R2" AP2-00000 119.806,18.767 r180 top
R102 "R2" AP2-00000 110.867,29.079 r270 top
R104 "R2" AP2-00000 109.131,24.828 r90 top
R105 "R2" AP2-00000 94.949,33.353 r180 top
R106 "R2" AP2-00001 99.105,60.827 r180 top
R107 "R2" AP2-00001 99.105,59.027 r180 top
R108 "R2" AP2-00001 99.105,57.227 r180 top
R109 "R2" AP2-00001 120.688,60.828 r0 top
R110 "R2" AP2-00001 120.688,59.028 r0 top
R111 "R2" AP2-00001 120.688,57.228 r0 top
R112 "R2" AP2-00000 99.1,55.6 r180 top
R113 "R2" AP2-00000 117.188,60.828 r180 top
R114 "R2" AP2-00000 117.188,59.028 r180 top
R115 "R2" AP2-00000 117.188,57.228 r180 top
R117 "R2" AP2-00001 23.243,20.925 r90 top
R118 "R2" AP2-00000 24.797,20.605 r270 top
R119 "R2" AP2-00001 30.5,17 r90 top
R120 "R2" AP2-00001 28.75,12.7 r0 top
R121 "R2" AP2-00000 31.414,9.685 r270 top
R122 "R2" AP2-00001 33.983,7.842 r0 top
R123 "R2" AP2-00001 7,21.5 r0 top
SW1 "SW_SPDT" AP8-00431 14.9,6 r270 top
SW2 "PUSHBUTTON1" AP8-00137 27.635,3.941 r0 top
TP1 "TESTPOINT" AP8-00010 123.838,70.981 r90 top
TP2 "TESTPOINT" AP8-00010 123.838,68.481 r90 top
TP3 "Through hole with 10mil annular ring" AP8-00722 95.538,70.981 r90 top
TP4 "Through hole with 10mil annular ring" AP8-00722 95.538,68.481 r0 top
TP5 "TESTPOINT" AP8-00010 123.838,65.981 r90 top
TP6 "Through hole with 10mil annular ring" AP8-00722 95.538,65.981 r90 top
TP7 "TESTPOINT" AP8-00010 14.95,110.135 r90 top
TP8 "TESTPOINT" AP8-00010 56.817,110.135 r90 top
TP9 "TESTPOINT" AP8-00010 98.724,110.135 r90 top
TP10 "TESTPOINT" AP8-00010 36.973,16.918 r90 top
TP11 "TESTPOINT" AP8-00010 41.49,16.842 r90 top
TP12 "TESTPOINT" AP8-00010 7.65,10.35 r180 top
TP13 "Through hole with 10mil annular ring" AP8-00722 25.168,78.39 r90 top
TP14 "TESTPOINT" AP8-00010 123.838,59.181 r90 top
TP15 "TESTPOINT" AP8-00010 88.935,70.702 r90 top
TP16 "Through hole with 10mil annular ring" AP8-00722 67.11,77.658 r90 top
TP17 "TESTPOINT" AP8-00010 123.838,56.681 r90 top
TP18 "TESTPOINT" AP8-00010 123.838,61.681 r90 top
TP19 "Through hole with 10mil annular ring" AP8-00722 108.91,78.326 r90 top
TP20 "TESTPOINT" AP8-00010 83.235,67.162 r90 top
TP21 "Through hole with 10mil annular ring" AP8-00722 21.135,86.512 r90 top
TP22 "Mounting hole dia should be 1.6mm. Refer A08-2059" AP8-00710 40.285,69.312 r90 top
TP23 "Through hole with 10mil annular ring" AP8-00722 61.708,86.342 r90 top
TP24 "Mounting hole dia should be 1.6mm. Refer A08-2059" AP8-00710 103.81,42.684 r90 top
TP25 "Through hole with 10mil annular ring" AP8-00722 104.708,86.492 r90 top
TP26 "Through hole with 10mil annular ring" AP8-00722 95.538,61.681 r90 top
TP27 "TESTPOINT" AP8-00010 47.451,100.028 r180 top
TP28 "Through hole with 10mil annular ring" AP8-00722 68.12,65.2 r180 top
TP35 "Through hole with 10mil annular ring" AP8-00722 95.538,59.181 r90 top
TP36 "Through hole with 10mil annular ring" AP8-00722 95.538,56.681 r90 top
TP38 "TESTPOINT" AP8-00010 29.883,27.173 r90 top
TP39 "TESTPOINT" AP8-00010 94.227,80.95 r90 top
TP40 "TESTPOINT" AP8-00010 27.257,19.962 r90 top
TP41 "TESTPOINT" AP8-00010 21.481,20.11 r90 top
TP42 "TESTPOINT" AP8-00010 31.7,12.7 r90 top
TP43 "TESTPOINT" AP8-00010 34.622,11.599 r90 top
TP44 "TESTPOINT" AP8-00010 21.93,7.046 r90 top
TP45 "TESTPOINT" AP8-00010 60.65,57.65 r90 top
TP46 "TESTPOINT" AP8-00010 64.6,108.208 r90 top
TP47 "TESTPOINT" AP8-00010 22.6,108.208 r90 top
TP48 "TESTPOINT" AP8-00010 71.25,110.135 r90 top
TP49 "TESTPOINT" AP8-00010 67.839,92.395 r90 top
TP50 "TESTPOINT" AP8-00010 25.521,91.964 r90 top
TP51 "TESTPOINT" AP8-00010 29.235,110.135 r90 top
TP52 "TESTPOINT" AP8-00010 77.7,81.697 r90 top
TP53 "TESTPOINT" AP8-00010 35.7,81.697 r90 top
TP54 "TESTPOINT" AP8-00010 106.6,108.21 r90 top
TP55 "TESTPOINT" AP8-00010 110.139,91.791 r90 top
TP56 "TESTPOINT" AP8-00010 113.4,110.135 r90 top
TP57 "TESTPOINT" AP8-00010 120.857,81.277 r90 top
TP58 "TESTPOINT" AP8-00010 7.042,38.358 r90 top
TP60 "TESTPOINT" AP8-00010 94.138,63.981 r90 top
TP61 "TESTPOINT" AP8-00010 83.077,76.1 r90 top
TP62 "TESTPOINT" AP8-00010 100.453,30.003 r90 top
TP63 "TESTPOINT" AP8-00010 122.64,15 r90 top
TP64 "TESTPOINT" AP8-00010 115.488,25.858 r90 top
TP65 "TESTPOINT" AP8-00010 116.909,17.128 r90 top
TP66 "TESTPOINT" AP8-00010 111.576,10.634 r90 top
TP67 "TESTPOINT" AP8-00010 99.453,26.431 r90 top
TP68 "TESTPOINT" AP8-00010 124.525,7.531 r90 top
TP72 "TESTPOINT" AP8-00010 93.346,55.698 r90 top
U1 "4Bit_BiDir_VLT" AP6-00057 106.586,67.668 r0 top
U2 "NCP5106" AP6-00000 13.023,78.987 r90 top
U3 "NCP5106" AP6-00000 53.845,78.975 r90 top
U4 "NCP5106" AP6-00000 96.545,78.975 r90 top
U5 "NCV47710" AP6-00427 13.75,16.75 r180 top
U6 "VOLTREG" AP6-00041 36.969,24.312 r90 top
U7 "LTC2050HS5#PBF" AP6-00087 65.9,81.4 r180 top
U8 "LTC2050HS5#PBF" AP6-00087 23.95,81.4 r180 top
U9 "LTC2050HS5#PBF" AP6-00087 107.661,81.409 r180 top
U10 "AT30TSx75x" AP6-00186 89.167,88.122 r270 top
U11 "AT25DF081A" AP8-00417 114.395,34.89 r0 top
U12 "ATSHA204A-SWI" AP6-00409 103.711,32.943 r270 top
U13 "Mouser: 1016-1588-2-ND" AP6-00338 103.834,24.967 r90 top
U14 "TPS2112" AP6-00054 108.884,18.067 r180 top
U15 "" AP6-00087 82.371,73.108 r270 top
U16 "4Bit_BiDir_VLT" AP6-00057 106.586,58.996 r0 top
U17 "STMPS2161" AP6-00087 111.822,25.376 r270 top

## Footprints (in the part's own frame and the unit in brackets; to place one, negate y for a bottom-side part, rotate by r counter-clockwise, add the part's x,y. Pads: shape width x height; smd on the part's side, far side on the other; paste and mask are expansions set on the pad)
AP1-00001 [mm] "Standard 0402 SMD capacitor footprint"
  rect 0.9x0.6 smd: 1(-0.55,0) 2(0.55,0)
  silkscreen extent -1.25,-0.55 1.25,0.55, body extent -0.5,-0.3 0.5,0.3, height 0.2
AP1-00002 [mm]
  rect 1x0.95 smd: 1(-0.8,0) 2(0.8,0)
  silkscreen extent -1.55,-0.72 1.55,0.72, body extent -0.8,-0.4 0.8,0.4, height 0.3
AP1-00003 [mm]
  rect 1.35x1.5 smd: 1(-0.825,0) 2(0.825,0)
  silkscreen extent -1.78,-1 1.78,1, body extent -1,-0.63 1,0.63, height 0.78
AP1-00012 [mm]
  rect 3.4x1 smd: 1(-3.05,0) 2(3.05,0)
  silkscreen extent -4.25,-4.25 4.25,4.25, body extent -4.25,-4.25 4.25,4.25, height 10.2
AP1-00013 [mm]
  rect 2.45x2.3 smd: 1(-2.375,0) 2(2.375,0)
  silkscreen extent -3.85,-2 3.85,2, body extent -3.1,-1.7 3.1,1.7, height 2.6
AP1-00015 [mm]
  rect 1.25x2.7 smd: 1(-1.525,0) 2(1.525,0)
  silkscreen extent -2.4,-1.6 2.4,1.6, body extent -1.65,-1.25 1.55,1.25, height 0.95
AP1-00025 [mm]
  rect 4.3x1.35 smd: 1(-3.95,0) 2(3.95,0)
  silkscreen extent -5.6,-5.25 5.6,5.25, body extent -5.6,-5.25 5.6,5.25, height 10.5
AP1-00026 [mm]
  rect 0.95x1.75 smd: 1(-1.475,0) 2(1.475,0)
  silkscreen extent -2.2,-1.12 2.2,1.12, body extent -1.6,-0.8 1.6,0.8, height 1
AP1-00036 [mm] "SMD capacitors: 3216-18 EIA Case 1206, polarized"
  rect 0.95x1.75 smd: 1(-1.475,0) 2(1.475,0)
  silkscreen extent -2.95,-1.12 2.2,1.12, body extent -1.6,-0.8 1.6,0.8, height 1
AP1-00039 [mil] "Capacitor 0603 Hight 0.8mm"
  rect 30x30 smd: 1(-27.5,0) 2(27.5,0)
  silkscreen extent -52,-24 51,24, body extent -31,-16 32,16, height 12
AP1-00053 [mm] "Chip Capacitor, 2-Leads, Body 1.0x0.5mm, IPC High Density"
  rect 0.65x0.5 smd: 1(-0.475,0) 2(0.475,0)
  body extent -0.5,-0.3 0.5,0.3, height 0.2
AP1-00069 [mm] "0805 Cap"
  rect 0.9x1.35 smd: 1(-1.05,0) 2(1.05,0)
  silkscreen extent -0.4,-0.58 0.4,0.58, body extent -1,-0.6 1,0.6, height 1.25
AP2-00000 [mm] "Standard 0402 SMD resistor footprint"
  rect 0.8x0.65 smd: 1(-0.6,0) 2(0.6,0)
  silkscreen extent -1.25,-0.58 1.25,0.58, body extent -0.5,-0.3 0.5,0.3, height 0.2
AP2-00001 [mm]
  rect 1x0.95 smd: 1(-0.85,0) 2(0.85,0)
  silkscreen extent -1.6,-0.72 1.6,0.72, body extent -0.8,-0.4 0.8,0.4, height 0.3
AP2-00002 [mm]
  rect 1.2x1.35 smd: 1(-0.95,0) 2(0.95,0)
  silkscreen extent -1.8,-0.92 1.8,0.92, body extent -1,-0.62 1,0.63, height 0.78
AP2-00003 [mm]
  rect 1.4x1.8 smd: 1(-1.45,0) 2(1.45,0)
  silkscreen extent -2.4,-1.15 2.4,1.15, body extent -1.6,-0.8 1.6,0.8, height 1
AP2-00011 [mm] "Chip Resistor, 2-Leads, Body 1,0x0,5mm, IPC High Density"
  rect 0.6x0.55 smd: 1(-0.5,0) 2(0.5,0)
  body extent -0.5,-0.3 0.5,0.3, height 0.2
AP2-00018 [mm]
  rect 2x2.4 smd: 1(-3,0) 2(3,0)
  silkscreen extent -4.5,-3 4.5,2.9, body extent -4,-2.7 4,2.7, height 3.18
AP2-00080 [mm]
  rect 3.94x5.84 smd: 1(-4.575,0) 2(4.575,0)
  silkscreen extent -7.5,-4.2 7.5,4.2, body extent -5.78,-3.41 5.78,3.41, height 3.68
AP3-00002 [mm]
  rect 1.25x1.5 smd: 1(-0.275,0.3) 2(1.475,0.3)
  silkscreen extent -1.18,-0.7 2.37,1.3, body extent -0.4,-0.3 1.6,0.9, height 0.95
AP3-00005 [mm]
  rect 0.7x0.7 smd: 1(-0.7,0) 2(0.7,0)
  silkscreen extent -1.3,-0.6 1.3,0.6, body extent -0.83,-0.41 0.82,0.41, height 0.8
AP4-00001 [mm]
  rect 1.1x1 smd: 1(0,0)
  rect 1.1x0.6 smd: 2(0,-1.7) 3(2.1,-1.7) 4(2.1,0.2)
  silkscreen extent -0.82,-2.5 2.93,1, body extent -0.13,-2.2 2.23,0.7, height 1.21
AP4-00002 [mm]
  rect 2.5x2.15 smd: 1(-2.05,0) 2(2.05,0)
  silkscreen extent -3.56,-2.29 3.56,2.29, body extent -2.8,-1.97 2.8,1.97, height 2.45
AP4-00013 [mm] "0805 diode footprint"
  rect 1.2x1.2 smd: 1(-1.05,0) 2(1.05,0)
  silkscreen extent -2.16,-1 1.85,1, body extent -1,-0.63 1,0.63, height 1.1
AP4-00036 [mm] "Molded Diode, 2-Leads, Body 1,2x0,8mm, IPC Medium Density"
  rect 0.4x0.4 smd: 1(-0.7,0) 2(0.7,0)
  silkscreen extent -1.43,-0.7 1.43,0.7, body extent -0.8,-0.4 0.8,0.4, height 0.7
AP4-00038 [mm] "SMA 403D-02"
  rect 2.55x2 smd: 1(-2.025,0) 2(2.025,0)
  silkscreen extent -3.68,-1.5 2.8,1.52, body extent -2.8,-1.46 2.8,1.46, height 2.41
AP4-00142 [mm]
  rect 1.25x2 smd: 1(-1.875,0) 2(1.875,0)
  silkscreen extent -2.8,-1.3 2.8,1.3, body extent -1.87,-0.8 1.83,0.8, height 1.6
AP5-00001 [mm]
  rect 0.85x0.35 smd: 1(-0.925,0.65) 2(-0.925,0) 3(-0.925,-0.65) 4(0.925,-0.65) 5(0.925,0) 6(0.925,0.65)
  silkscreen extent -1.6,-1.35 1.6,1.35, body extent -1.05,-1 1.05,1, height 0.95
AP5-00002 [mm] "SOT-23 Package"
  rect 1.3x0.6 smd: 1(-1.05,0.95) 2(-1.05,-0.95) 3(1.05,0)
  silkscreen extent -1.95,-1.78 1.95,1.78, body extent -1.25,-1.46 1.23,1.46, height 1
AP5-00005 [mm]
  rect 1.5x2.5 smd: 1(-2.3,-6.9) 3(2.3,-6.9)
  rect 7x7 smd: 2(0,0)
  silkscreen extent -4,-8.51 4,4.06, body extent -3.3,-3.05 3.3,3.05, height 2.3
AP5-00048 [mm]
  rect 0.75x1 smd: 1(-1.895,0) 1(-0.625,0) 1(0.645,0) 2(1.915,0) 3(0.05,3.55)
  Top Layer region: 2.29,1.89 2.29,1.465 -2.27,1.465 -2.27,1.89 -2.765,1.89 -2.765,2.845 -2.27,2.845 -2.27,5.995 -1.52,5.995 -1.52,5.52 1.54,5.52 1.54,5.995 2.29,5.995 2.29,2.795 2.785,2.795 2.785,1.89
  silkscreen extent -3.3,-1.55 3.3,6.5, body extent -2.58,0 2.58,6.15, height 1
AP6-00000 [mm]
  rect 2.2x0.6 smd: 1(0,0) 2(0,-1.27) 3(0,-2.54) 4(0,-3.81) 5(4.85,-3.81) 6(4.85,-2.54) 7(4.85,-1.27) 8(4.85,0)
  silkscreen extent -1.33,-4.65 6.17,1.35, body extent -0.67,-4.4 5.52,0.6, height 1.7
AP6-00041 [mm] "DPAK"
  rect 3x1.6 smd: 1(-4.35,2.28) 3(-4.35,-2.28)
  rect 6.7x6.7 smd: 2(2.3,0)
  silkscreen extent -4.27,-3.3 -1.45,3.75, body extent -2.15,-3.3 4.05,3.3, height 2.4
AP6-00054 [mm]
  rect 1.7x0.35 smd: 1(-2.85,0.975) 2(-2.85,0.325) 3(-2.85,-0.325) 4(-2.85,-0.975) 5(2.85,-0.975) 6(2.85,-0.325) 7(2.85,0.325) 8(2.85,0.975)
  silkscreen extent -2.98,1.58 -2.73,1.82, body extent -3.23,-1.55 3.23,1.55, height 1.25
AP6-00057 [mm]
  oval 1.6x0.35 smd: 1(-2.875,1.95) 2(-2.875,1.3) 3(-2.875,0.65) 4(-2.875,0) 5(-2.875,-0.65) 6(-2.875,-1.3) 7(-2.875,-1.95) 8(2.875,-1.95) 9(2.875,-1.3) 10(2.875,-0.65) 11(2.875,0) 12(2.875,0.65) 13(2.875,1.3) 14(2.875,1.95)
  silkscreen extent -3.93,-2.8 3.93,2.8, body extent -2.25,-2.55 2.25,2.55, height 1.1
AP6-00087 [mm]
  rect 1.05x0.65 smd: 1(-1.225,0.953) 2(-1.225,0) 3(-1.225,-0.953) 4(1.225,-0.953) 5(1.225,0.953)
  silkscreen extent -2,-1.75 2,1.75, body extent -1.5,-1.5 1.5,1.5, height 1.3
AP6-00186 [mm] "8M2, 8-lead 2.0x3.0 mm Body, 0.50 mm Pitch,  WDFN, Very Very Thin, Dual No Lead Package"
  round 0.264 on Top Paste: 0(-0.425,0.4) 0(-0.425,-0.4) 0(0,0) 0(0.425,0.4) 0(0.425,-0.4)
  rect 0.85x0.3 smd: 1(-1.475,0.75) 2(-1.475,0.25) 3(-1.475,-0.25) 4(-1.475,-0.75) 5(1.475,-0.75) 6(1.475,-0.25) 7(1.475,0.25) 8(1.475,0.75)
  rect 1.3x1.4 smd paste-0.7: 9(0,0)
  silkscreen extent -2.26,-1.3 2.2,1.33, body extent -1.53,-1 1.53,1, height 0.76
AP6-00338 [mm] "8-lead 3.0x2.0 mm Body, 0.50 mm Pitch,  VDFN, Very Thin, Dual Flat No-Lead Package"
  round 0.4 on Top Paste: 0(-0.425,-0.4) 0(-0.425,0.4) 0(0,0) 0(0.425,-0.4) 0(0.425,0.4)
  rect 0.6x0.25 smd: 1(-1.4,0.75) 2(-1.4,0.25) 3(-1.4,-0.25) 4(-1.4,-0.75) 5(1.4,-0.75) 6(1.4,-0.25) 7(1.4,0.25) 8(1.4,0.75)
  rect 1.6x1.5 smd paste-0.7: 9(0,0)
  silkscreen extent -2.26,-1.3 2.2,1.33, body extent -1.53,-1 1.53,1, height 0.92
AP6-00409 [mm]
  rect 0.7x0.3 smd mask+0.075: 1(-1.45,0.75) 2(-1.45,0.25) 3(-1.45,-0.25) 4(-1.45,-0.75) 5(1.45,-0.75) 6(1.45,-0.25) 7(1.45,0.25) 8(1.45,0.75)
  rect 1.4x1.6 smd paste-0.025 mask+0.075: 9(0,0)
  silkscreen extent -2,-1.1 2,1.45, body extent -1.55,-1.05 1.55,1.05, height 0.6
AP6-00427 [mm] "SOIC, 8-Leads, Body 4.90x3.90mm, Pitch 1.27mm, Thermal Pad 3.20.2x2.15.2mm, IPC Medium Density"
  oval 2.1x0.6 smd: 1(-2.425,1.905) 2(-2.425,0.635) 3(-2.425,-0.635) 4(-2.425,-1.905) 5(2.425,-1.905) 6(2.425,-0.635) 7(2.425,0.635) 8(2.425,1.905)
  rect 2.15x3.2 smd: 9(0,0)
  silkscreen extent -2.55,-2.45 0.98,2.88, body extent -1.95,-2.45 1.95,2.45, height 1.75
AP8-00010 [mm] "Testpad 50mil"
  round 1.27 smd paste-0.635: 1(0,0)
  silkscreen extent -0.9,-0.9 0.9,0.9
AP8-00137 [mm]
  rect 2.25x1 smd: 1(-2.75,2) 2(2.75,2) 3(-2.75,-2) 4(2.75,-2)
  silkscreen extent -4.25,-3.25 4.25,3.25, body extent -3.4,-3.21 3.4,3.22, height 3.47
AP8-00177 [mm]
  rect 1.7x1.7 / inner round 1.7 / far side round 1.7 hole 1: 1(-6.35,0) 2(-3.81,0) 3(-1.27,0) 4(1.27,0) 5(3.81,0) 6(6.35,0)
  silkscreen extent -7.62,-1.27 7.62,1.27, body extent -7.62,-1.25 7.52,1.25, height 8.2
AP8-00192 [mm]
  silkscreen extent -4,-4 4,4, body extent -4,-4 4,4, height 2.79
AP8-00249 [mm]
  rect 6x6 smd: 1(-8.5,0) 2(8.5,0)
  silkscreen extent -13,-6 13,6, body extent -12.5,-5.5 12.5,5.5, height 13.2
AP8-00317 [mm] "Placement area for 18x6mm sticker"
  silkscreen extent 0,0 18,6
AP8-00417 [mil]
  rect 24x80 smd: 1(0,0)
  oval 24x80 smd: 2(50,0) 3(100,0) 4(150,0) 5(150,220) 6(100,220) 7(50,220) 8(0,220)
  silkscreen extent -25,60 175,160, body extent -22,-6 171,222, height 57
AP8-00431 [mm] "3pin DIP switch 90deg"
  round 1.4 hole 0.8: 1(0,0) 2(0,2.54) 3(0,-2.54)
  silkscreen extent 1,-5 7.5,5, body extent -0.5,-5 7.5,5, height 2
AP8-00525 [mm] "Jumper 2.54mm, 3D"
  body extent -2.49,-1.22 2.49,1.22, height 8.57
AP8-00622 [mm] "2x10 Right angle 2.54mm THM"
  rect 1.7x1.7 / inner round 1.7 / far side rect 1.7x1.7 hole 1: 1(-11.43,-1.27)
  rect 2.1x2.1 on Top Paste: 1(-11.43,-1.27) 2(-11.43,1.27) 3(-8.89,-1.27) 4(-8.89,1.27) 5(-6.35,-1.27) 6(-6.35,1.27) 7(-3.81,-1.27) 8(-3.81,1.27) 9(-1.27,-1.27) 10(-1.27,1.27) 11(1.27,-1.27) 12(1.27,1.27) 13(3.81,-1.27) 14(3.81,1.27) 15(6.35,-1.27) 16(6.35,1.27) 17(8.89,-1.27) 18(8.89,1.27) 19(11.43,-1.27) 20(11.43,1.27)
  round 1.7 hole 1: 2(-11.43,1.27) 3(-8.89,-1.27) 4(-8.89,1.27) 5(-6.35,-1.27) 6(-6.35,1.27) 7(-3.81,-1.27) 8(-3.81,1.27) 9(-1.27,-1.27) 10(-1.27,1.27) 11(1.27,-1.27) 12(1.27,1.27) 13(3.81,-1.27) 14(3.81,1.27) 15(6.35,-1.27) 16(6.35,1.27) 17(8.89,-1.27) 18(8.89,1.27) 19(11.43,-1.27) 20(11.43,1.27)
  silkscreen extent -12.85,2.77 12.85,5.31, body extent -12.7,-1.59 12.7,11.29, height 5
AP8-00628 [mm] "2x2 Right angle 2.54mm THM"
  rect 1.7x1.7 / inner round 1.7 / far side rect 1.7x1.7 hole 1: 1(-1.27,-1.27)
  rect 2.1x2.1 on Top Paste: 1(-1.27,-1.27) 2(-1.27,1.27) 3(1.27,-1.27) 4(1.27,1.27)
  round 1.7 hole 1: 2(-1.27,1.27) 3(1.27,-1.27) 4(1.27,1.27)
  silkscreen extent -2.69,2.77 2.67,5.31, body extent -2.54,-1.52 2.54,11.36, height 5
AP8-00710 [mm] "THM Test Point, 1.0mm Dia. Mounting Hole"
  round 1.7 hole 1: 1(0,0)
  rect 1.75x1.75 on Top Paste: 3(0,0)
  silkscreen extent -1.25,-1.25 1.25,1.25, body extent -1.25,-1.25 1.25,1.25, height 2.5
AP8-00722 [mil] "THM Test point"
  round 60 hole 40: 1(0,0)
  silkscreen extent -43,-43 43,43
AP8-00745 [mm] "THM Pin-header 1x3 100mil pitch, 1mm hole"
  rect 1.7x1.7 / inner round 1.7 / far side rect 1.7x1.7 hole 1: 1(-2.54,0)
  rect 2.1x2.1 on Top Paste: 1(-2.54,0) 2(0,0) 3(2.54,0)
  round 1.7 hole 1: 2(0,0) 3(2.54,0)
  silkscreen extent -3.81,-1.48 3.81,1.48, body extent -3.81,-1.27 3.81,1.27, height 8.38
AP8-00852 [mm] "Hirose, ZX Series, USB Micro-AB Recept-RA"
  rect 0.4x1.35 smd: 1(-1.3,2.8) 2(-0.65,2.8) 3(0,2.8) 4(0.65,2.8) 5(1.3,2.8)
  rrect52% 2.1x1.9 hole 0.825 slot 1.5 at 90 deg copper offset 0.437,0: 6(-4.088,0)
  rrect52% 2.1x1.9 on Top Paste: 6(-3.6,0) 7(3.6,0)
  rrect52% 2.1x1.9 hole 0.825 slot 1.5 at 90 deg copper offset -0.437,0: 7(4.088,0)
  rrect100% 1.05x1.25 hole 0.65 slot 0.85 at 90 deg: 8(-2.225,3.125) 9(2.225,3.125)
  rrect100% 1.05x1.25 on Top Paste: 8(-2.225,3.125) 9(2.225,3.125)
  Top Layer region: -2.05,-0.95 -0.25,-0.95 -0.25,0.95 -2.05,0.95
  Top Layer region: 0.25,-0.95 2.05,-0.95 2.05,0.95 0.25,0.95
  Top Layer pour cut-out: -3.75,1.975 3.75,1.975 3.75,-1.325 -3.75,-1.325
  Top Layer region: -2.6,0.95 -4.2,0.95 -4.294,0.941 -4.381,0.915 -4.434,0.891 -4.48,0.862 -4.52,0.832 -4.565,0.791 -4.596,0.753 -4.622,0.716 -4.647,0.673 -4.66,0.64 -4.676,0.6 -4.688,0.55 -4.696,0.505 -4.7,0.45 -4.7,-0.45 -4.696,-0.503 -4.689,-0.548 -4.677,-0.599 -4.661,-0.641 -4.641,-0.683 -4.617,-0.724 -4.589,-0.761 -4.56,-0.797 -4.521,-0.831 -4.483,-0.86 -4.439,-0.888 -4.397,-0.908 -4.354,-0.924 -4.301,-0.939 -4.248,-0.946 -4.2,-0.95 -2.6,-0.95
  Top Layer region: 2.6,-0.95 4.2,-0.95 4.294,-0.941 4.381,-0.915 4.434,-0.891 4.48,-0.862 4.52,-0.832 4.565,-0.791 4.596,-0.753 4.622,-0.716 4.647,-0.673 4.66,-0.64 4.676,-0.6 4.688,-0.55 4.696,-0.505 4.7,-0.45 4.7,0.45 4.696,0.503 4.689,0.548 4.677,0.599 4.661,0.641 4.641,0.683 4.617,0.724 4.589,0.761 4.56,0.797 4.521,0.831 4.483,0.86 4.439,0.888 4.397,0.908 4.354,0.924 4.301,0.939 4.248,0.946 4.2,0.95 2.6,0.95
  Bottom Layer region: 2.6,-0.95 4.2,-0.95 4.294,-0.941 4.381,-0.915 4.434,-0.891 4.48,-0.862 4.52,-0.832 4.565,-0.791 4.596,-0.753 4.622,-0.716 4.647,-0.673 4.66,-0.64 4.676,-0.6 4.688,-0.55 4.696,-0.505 4.7,-0.45 4.7,0.45 4.696,0.503 4.689,0.548 4.677,0.599 4.661,0.641 4.641,0.683 4.617,0.724 4.589,0.761 4.56,0.797 4.521,0.831 4.483,0.86 4.439,0.888 4.397,0.908 4.354,0.924 4.301,0.939 4.248,0.946 4.2,0.95 2.6,0.95
  Bottom Layer region: -2.6,0.95 -4.2,0.95 -4.294,0.941 -4.381,0.915 -4.434,0.891 -4.48,0.862 -4.52,0.832 -4.565,0.791 -4.596,0.753 -4.622,0.716 -4.647,0.673 -4.66,0.64 -4.676,0.6 -4.688,0.55 -4.696,0.505 -4.7,0.45 -4.7,-0.45 -4.696,-0.503 -4.689,-0.548 -4.677,-0.599 -4.661,-0.641 -4.641,-0.683 -4.617,-0.724 -4.589,-0.761 -4.56,-0.797 -4.521,-0.831 -4.483,-0.86 -4.439,-0.888 -4.397,-0.908 -4.354,-0.924 -4.301,-0.939 -4.248,-0.946 -4.2,-0.95 -2.6,-0.95
  silkscreen extent -4.05,1.22 4.05,3.13, body extent -4.32,-2.65 4.33,3.25, height 2.78
AP8-00916 [mm]
  rect 1.2x2.75 smd: 0(-10.35,3) 0(10.35,3)
  round 0 hole 1.1 mask+0.55: 0(-10,-1.5)
  round 0 hole 1.6 mask+0.8: 0(10,-1.5)
  rect 0.3x1.55 smd: 1(-9.25,3.775) 2(-9,-3.775) 3(-8.75,3.775) 4(-8.5,-3.775) 5(-8.25,3.775) 6(-8,-3.775) 7(-7.75,3.775) 8(-7.5,-3.775) 9(-7.25,3.775) 10(-7,-3.775) 11(-6.75,3.775) 12(-4.5,-3.775) 13(-4.25,3.775) 14(-4,-3.775) 15(-3.75,3.775) 16(-3.5,-3.775) 17(-3.25,3.775) 18(-3,-3.775) 19(-2.75,3.775) 20(-2.5,-3.775) 21(-2.25,3.775) 22(-2,-3.775) 23(-1.75,3.775) 24(-1.5,-3.775) 25(-1.25,3.775) 26(-1,-3.775) 27(-0.75,3.775) 28(-0.5,-3.775) 29(-0.25,3.775) 30(0,-3.775) 31(0.25,3.775) 32(0.5,-3.775) 33(0.75,3.775) 34(1,-3.775) 35(1.25,3.775) 36(1.5,-3.775) 37(1.75,3.775) 38(2,-3.775) 39(2.25,3.775) 40(2.5,-3.775) 41(2.75,3.775) 42(3,-3.775) 43(3.25,3.775) 44(3.5,-3.775) 45(3.75,3.775) 46(4,-3.775) 47(4.25,3.775) 48(4.5,-3.775) 49(4.75,3.775) 50(5,-3.775) 51(5.25,3.775) 52(5.5,-3.775) 53(5.75,3.775) 54(6,-3.775) 55(6.25,3.775) 56(6.5,-3.775) 57(6.75,3.775) 58(7,-3.775) 59(7.25,3.775) 60(7.5,-3.775) 61(7.75,3.775) 62(8,-3.775) 63(8.25,3.775) 64(8.5,-3.775) 65(8.75,3.775) 66(9,-3.775) 67(9.25,3.775)
  silkscreen extent -11.25,-5.07 11.25,5.08, body extent -10.95,-4.35 10.95,4.35, height 4.09
AP8-00935 [mm] "SCREW-TERMINAL 5-POLE, 3.5MM, Through Hole"
  rect 1.7x1.7 / inner round 1.7 / far side round 1.7 hole 1.2: 1(0,0)
  round 1.7 hole 1.2: 2(3.5,0) 3(7,0) 4(10.5,0) 5(14,0)
  silkscreen extent -1.75,-3.1 15.75,4.5, body extent -2.32,-3.15 15.75,4.45, height 9.15
AP8-00979 [mm] "Terminal block 1 X2 7.62Pitch"
  rect 2x2 hole 1.3: 1(0,0)
  round 2 hole 1.3: 2(7.62,0)
  silkscreen extent -4.3,-6 11.9,5.6, body extent -3.85,-5.65 11.96,5.55, height 18.8
AP8-00980 [mm] "Terminal block 1 X3 7.62Pitch"
  rect 2x2 hole 1.3: 1(0,0)
  round 2 hole 1.3: 2(7.62,0) 3(15.24,0)
  silkscreen extent -4.3,-6 19.54,5.6, body extent -3.85,-5.65 19.58,5.55, height 18.3
AP9-00035 [mm] "PCB implemented strap, closed"
  round 0.4 smd paste-0.4: 1(-0.69,0) 2(0.69,0)
  oval 2.3x1.8 on Top Solder: 4(0,0)
  Top Layer lines w0.2: -0.675,0 0.55,0
  Top Layer lines w0.254: -0.48,0.51 -0.48,-0.48 ; 0.48,0.48 0.48,-0.51 ; -0.69,0.39 -0.69,-0.39 ; 0.69,0.39 0.69,-0.39 ; -0.25,0.65 ccw(c-0.25,0) -0.25,-0.65 -0.25,0.65 ; 0.25,0.65 cw(c0.25,0) 0.25,-0.65 0.25,0.65
AP9-00078 [mm] "Open Cuttable Link"
  round 0.4 smd paste-0.4: 1(-0.69,0) 2(0.69,0)
  Top Layer region: -0.1,0.783 -0.1,-0.777 -0.398,-0.717 -0.652,-0.548 -0.821,-0.295 -0.88,0.003 -0.88,0.003 -0.821,0.302 -0.652,0.555 -0.398,0.724 -0.1,0.783
  Top Layer region: 0.1,0.783 0.1,-0.777 0.398,-0.717 0.652,-0.548 0.821,-0.295 0.88,0.003 0.88,0.003 0.821,0.302 0.652,0.555 0.398,0.724 0.1,0.783
  Top Layer pour cut-out: 0,0 0,-0.9 -0.2,-0.9 -0.544,-0.831 -0.836,-0.636 -1.031,-0.344 -1.1,0 -1.1,0
  Top Layer pour cut-out: 0,0 0,0.9 -0.2,0.9 -0.544,0.831 -0.836,0.636 -1.031,0.344 -1.1,0 -1.1,0
  Top Layer pour cut-out: 0,0 0,-0.9 0.2,-0.9 0.544,-0.831 0.836,-0.636 1.031,-0.344 1.1,0 1.1,0
  Top Layer pour cut-out: 0,0 0,0.9 0.2,0.9 0.544,0.831 0.836,0.636 1.031,0.344 1.1,0 1.1,0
